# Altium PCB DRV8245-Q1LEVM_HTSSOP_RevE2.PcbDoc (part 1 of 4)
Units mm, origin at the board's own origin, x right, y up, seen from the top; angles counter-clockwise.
Board outline 81.9 x 103.6 mm, 4 copper layers (Top Layer, Signal Layer 1, Signal Layer 2, Bottom Layer), stack 1.554 mm thick; 187 components, 116 nets, 590 pads, 1182 vias.
Unrouted connection lines stored in the file: 116.
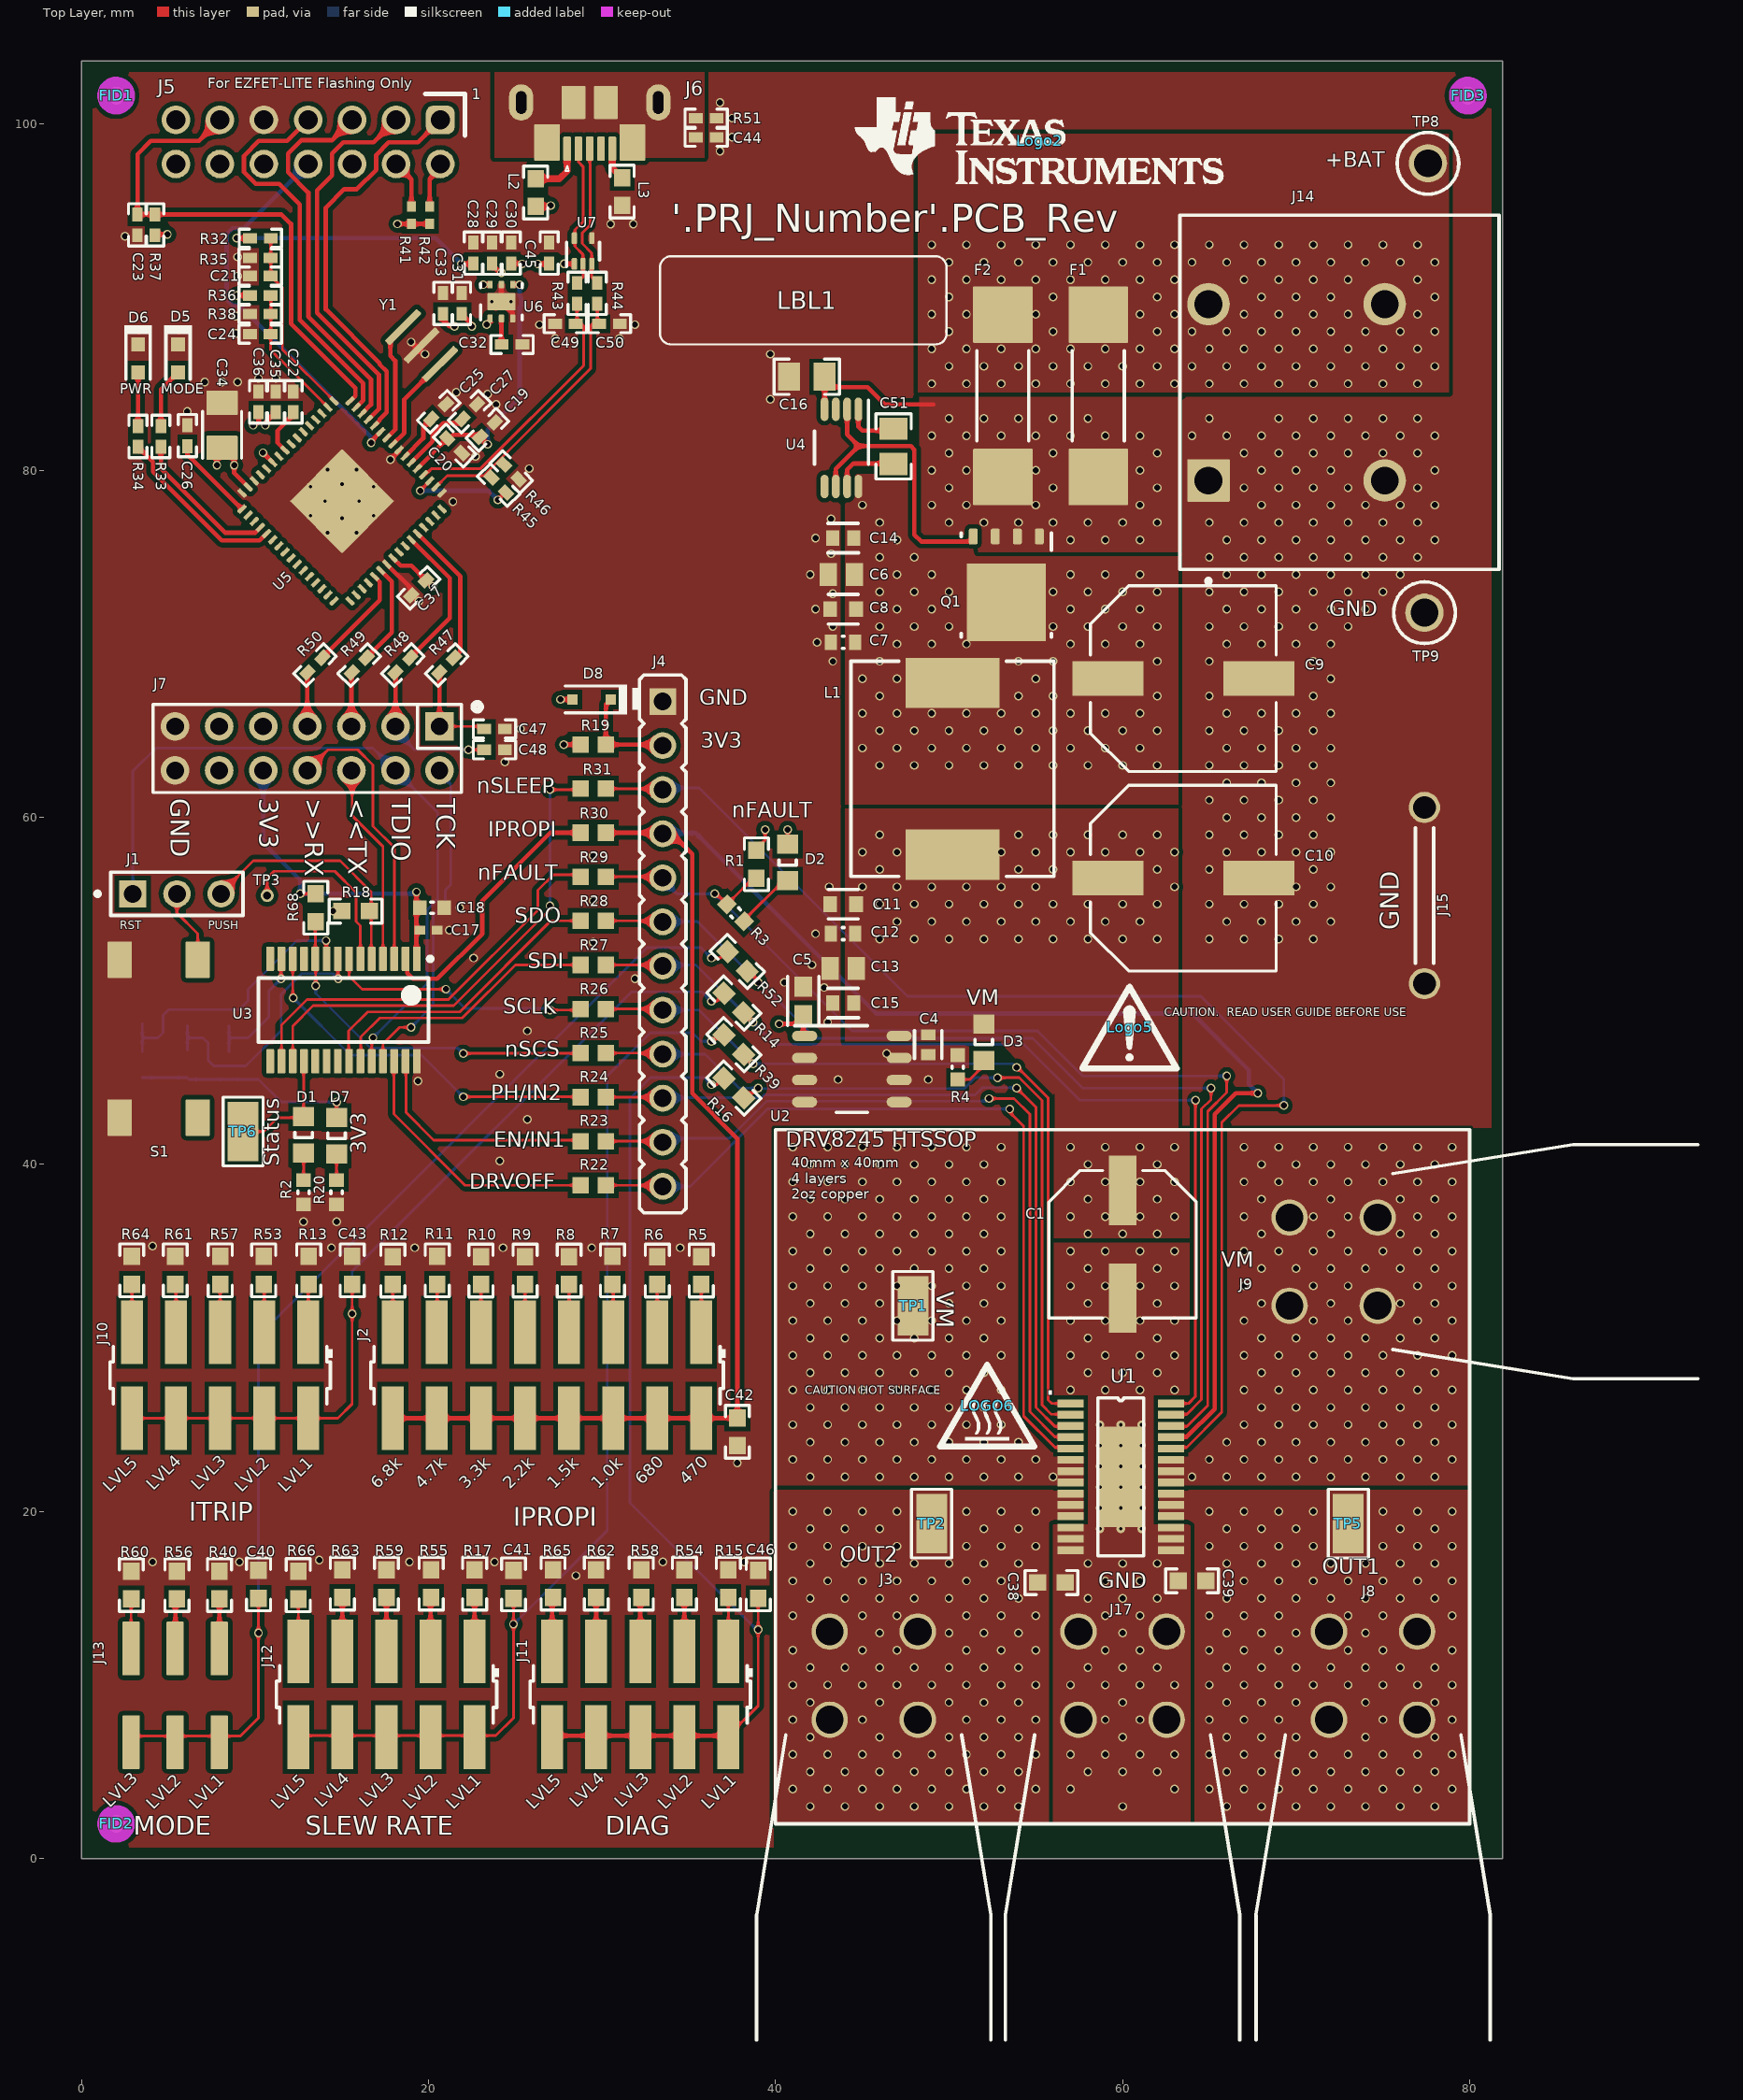
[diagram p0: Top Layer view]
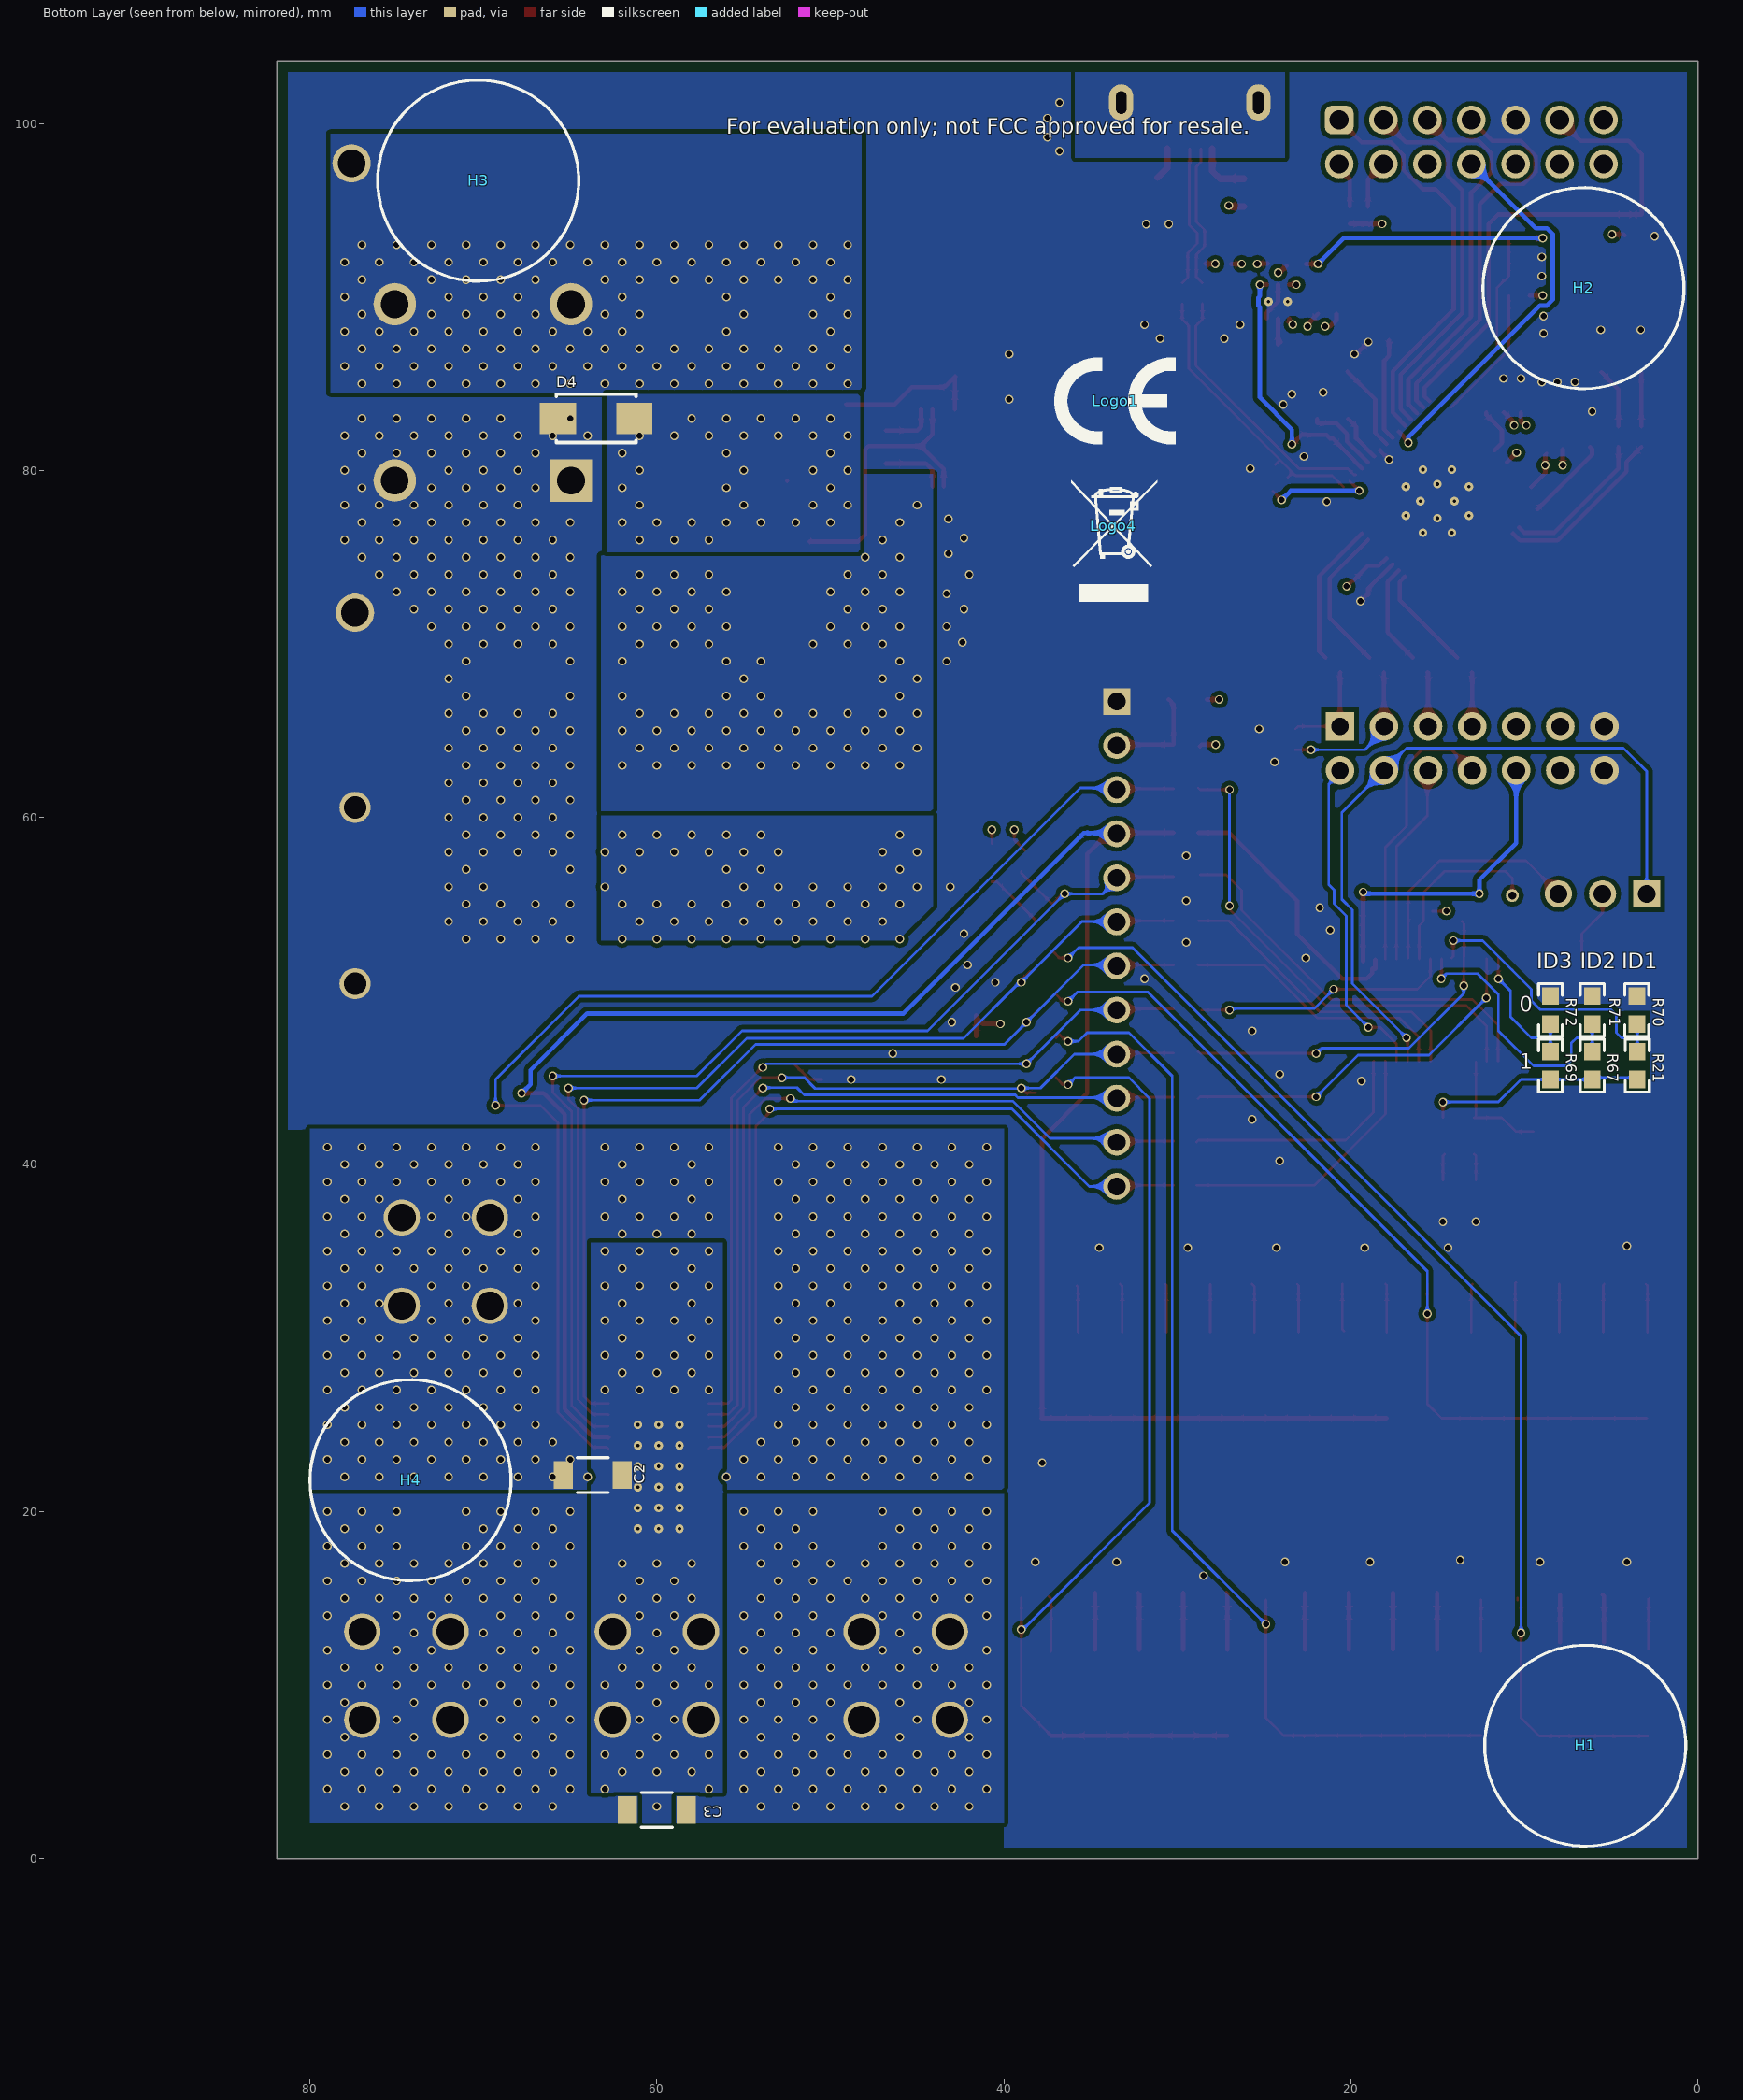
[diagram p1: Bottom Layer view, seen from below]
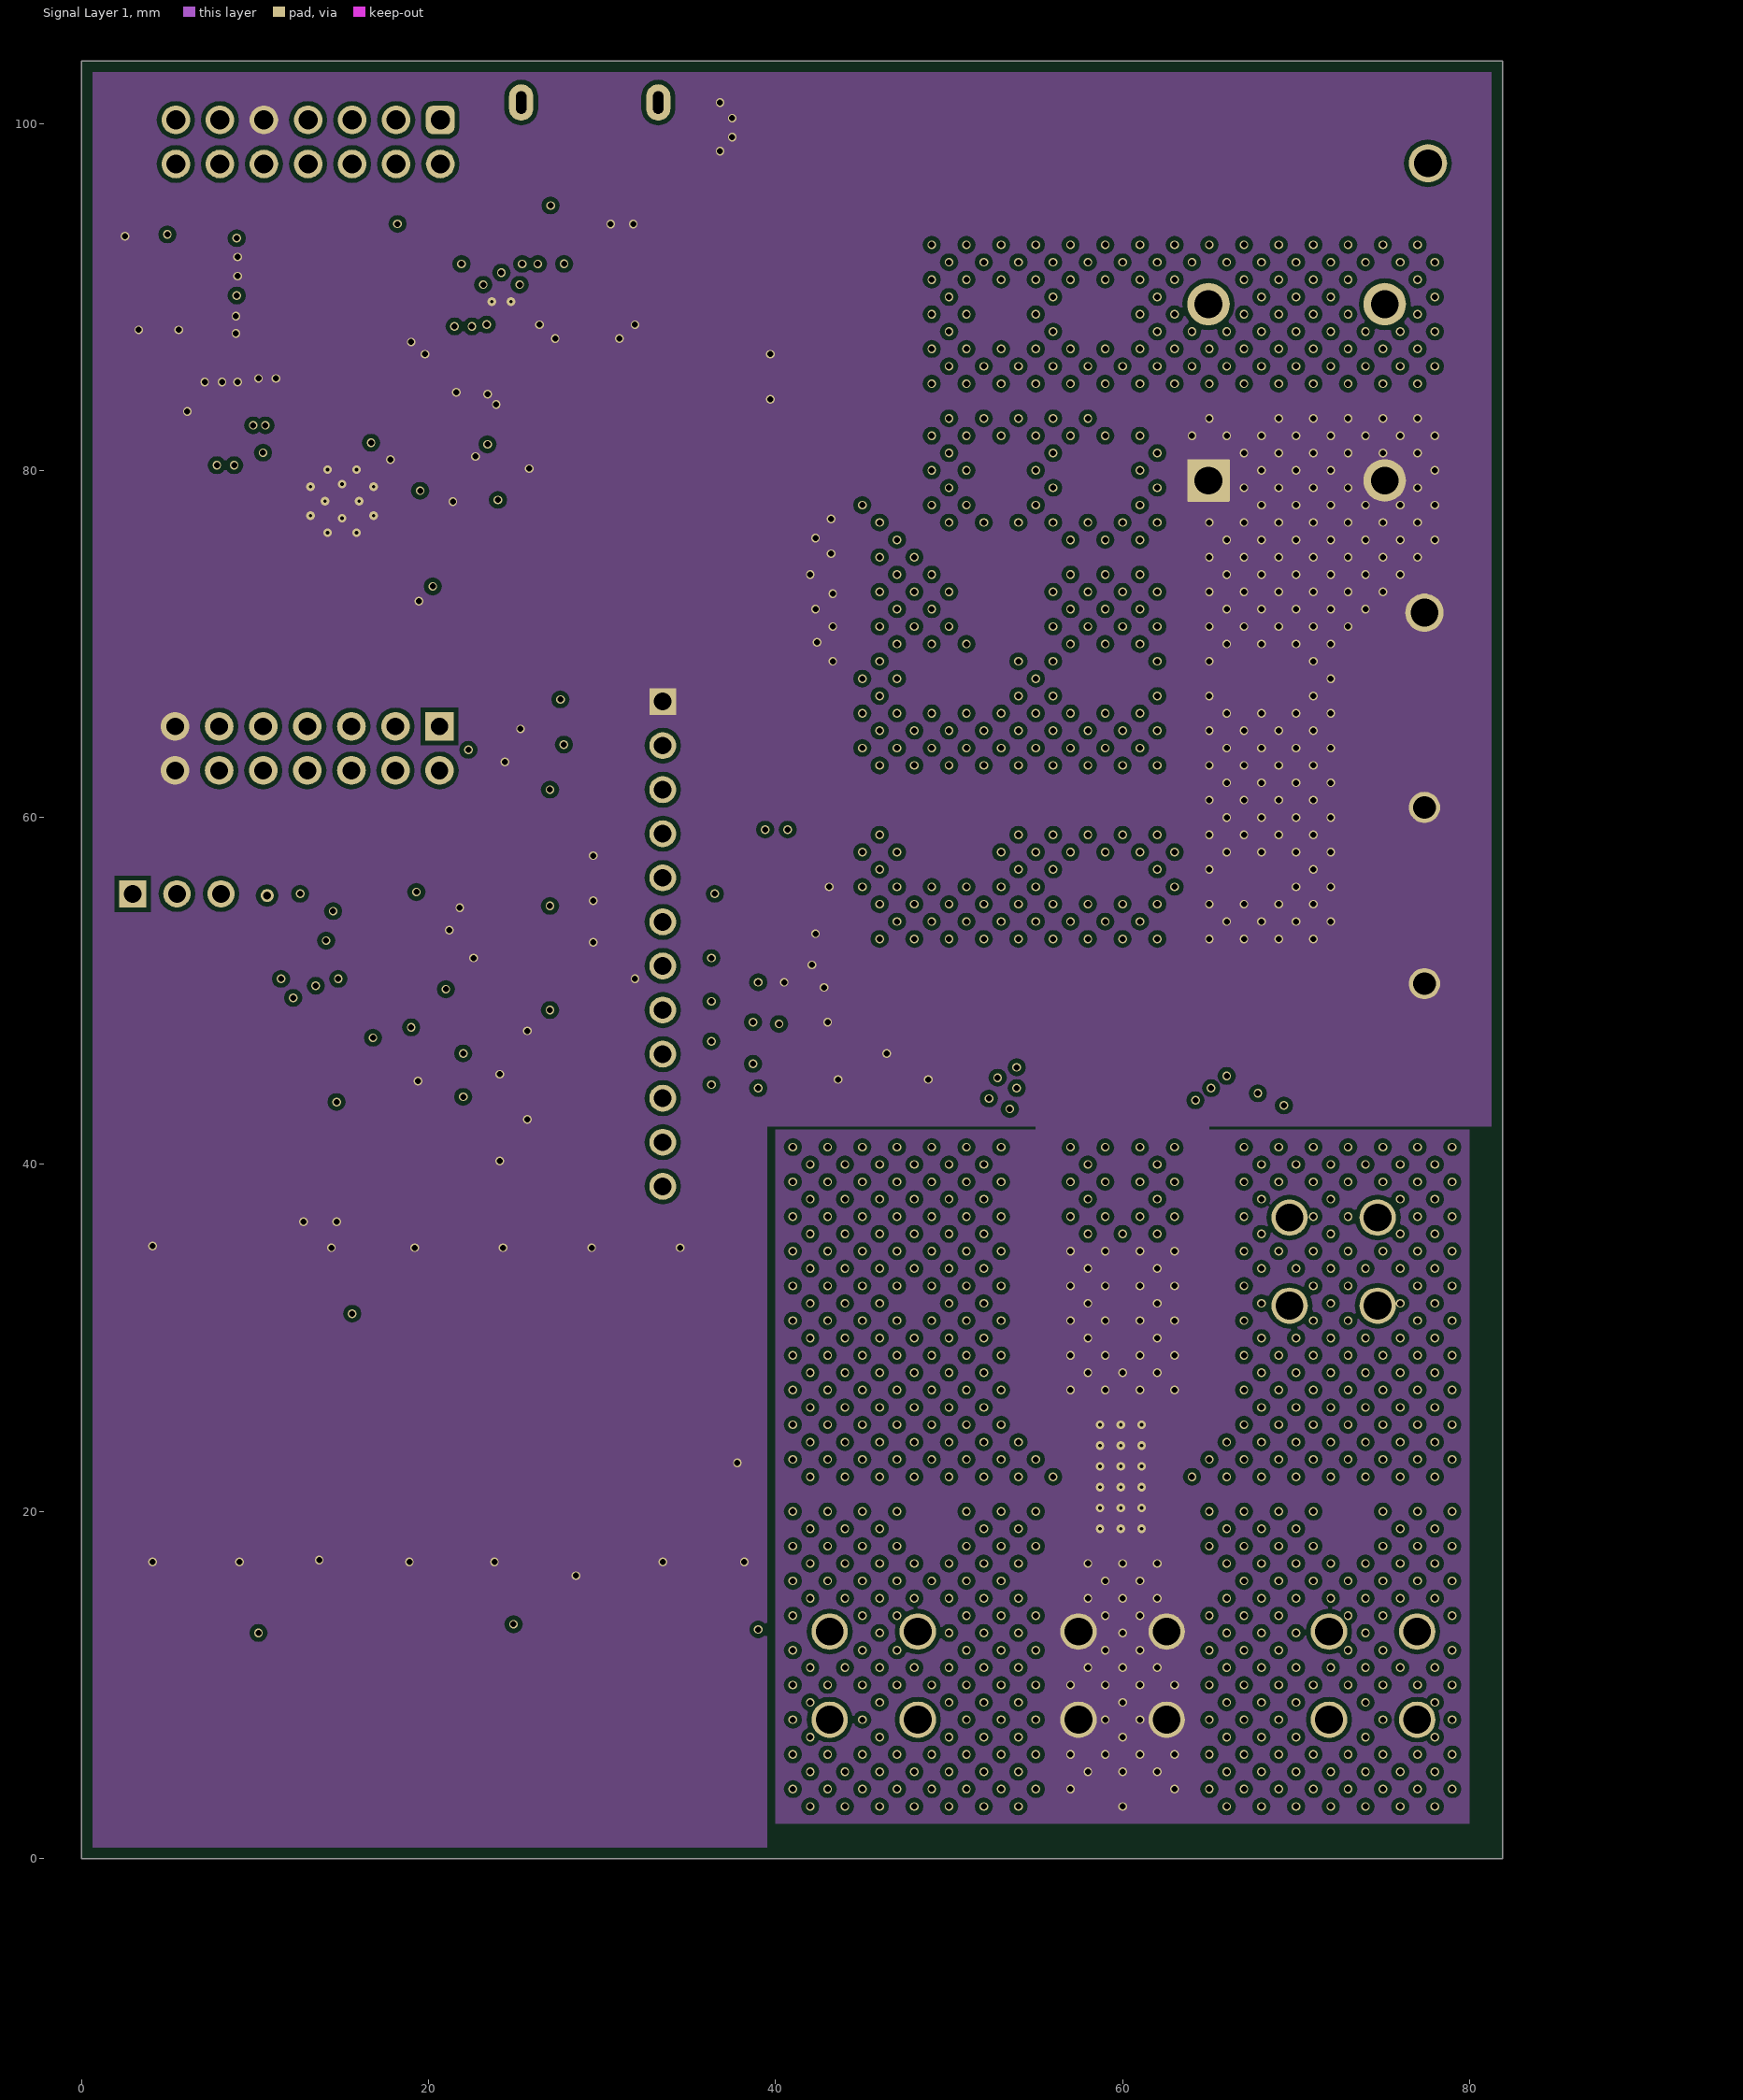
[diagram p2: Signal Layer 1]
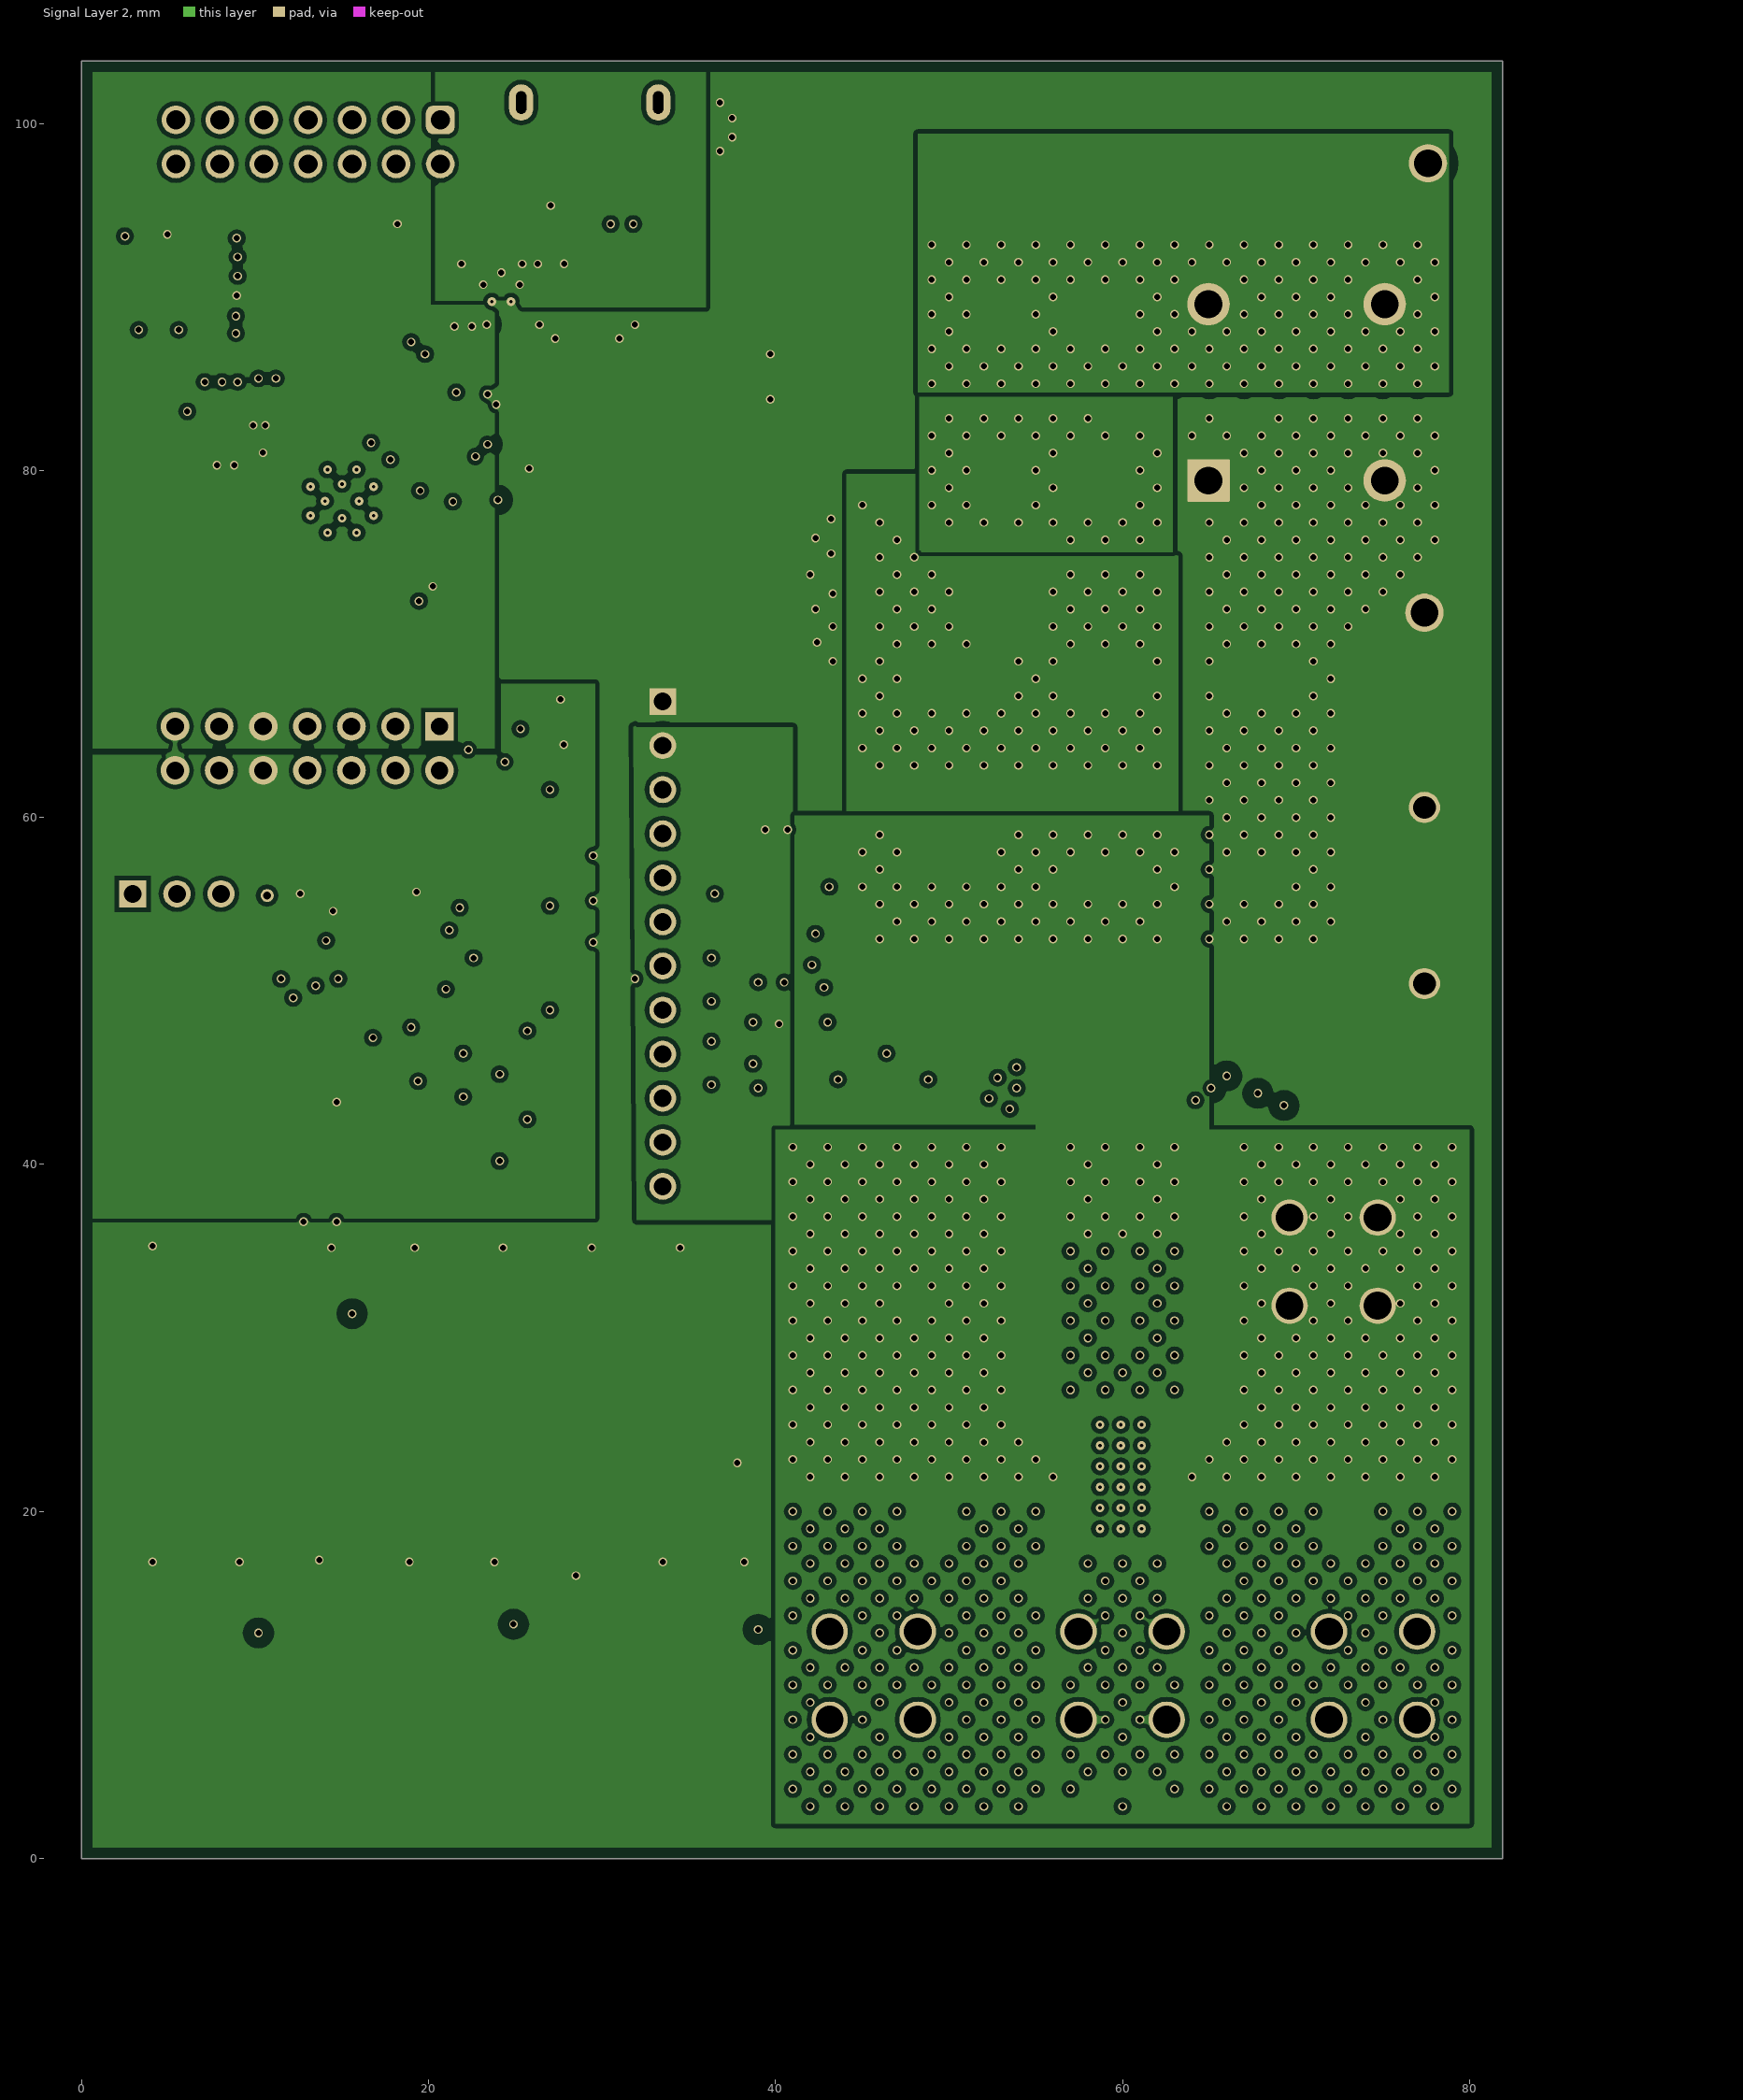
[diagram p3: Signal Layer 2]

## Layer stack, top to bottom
Top Solder: solder mask 0.0102, Solder Resist, Dk 3.5
Top Layer: signal copper 0.0711
Dielectric 1: prepreg 0.2896, FR4 370, Dk 4.2
Signal Layer 1: signal copper 0.0356
Dielectric 2: core 0.762, FR4 370, Dk 4.2
Signal Layer 2: signal copper 0.0356
Dielectric 3: prepreg 0.2896, FR4 370, Dk 4.2
Bottom Layer: signal copper 0.0711
Bottom Solder: solder mask 0.0102, Solder Resist, Dk 3.5

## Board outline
0,0 81.9,0 81.9,103.6 0,103.6

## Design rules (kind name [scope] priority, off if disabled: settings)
AcuteAngle [All] p1: minimum=4.50000000000000E+0001 checktracksonly=FALSE
AssemblyTestPointUsage [All] p1: valid=2
BoardOutlineClearance BoardOutlineClearance_MountingHoles [OnCopper and InComponentClass('Mounting Holes')] p1: gap=1 ignorepadtopadclearanceinfootprint=FALSE
BoardOutlineClearance BoardOutlineClearance_Poly [OnCopper and IsPoly] p2: gap=0.635 ignorepadtopadclearanceinfootprint=FALSE
BoardOutlineClearance [OnCopper and Not InComponentClass('Logo') and not InComponentClass('FiducialMark') and not InRegion(1000,500,4000,800) and not InPoly] p3: gap=1.905 ignorepadtopadclearanceinfootprint=FALSE
Clearance Clearance_92 [InNamedPolygon('TOP_LAYER_VM_P125')] p1: gap=0.254 ignorepadtopadclearanceinfootprint=TRUE except(0: Arc-Hole Track-Hole SMDPad-Hole THPad-Hole Via-Hole Fill-Hole Poly-Hole Region-Hole Text-Hole)
Clearance Clearance_91 [InNamedPolygon('TOP_LAYER_NONET_P-001')] p2: gap=0.254 ignorepadtopadclearanceinfootprint=TRUE except(0: Arc-Hole Track-Hole SMDPad-Hole THPad-Hole Via-Hole Fill-Hole Poly-Hole Region-Hole Text-Hole)
Clearance Clearance_90 [InNamedPolygon('BOTTOM_LAYER_OUT2_P211')] p3: gap=0.254 ignorepadtopadclearanceinfootprint=TRUE except(0: Arc-Hole Track-Hole SMDPad-Hole THPad-Hole Via-Hole Fill-Hole Poly-Hole Region-Hole Text-Hole)
Clearance Clearance_89 [InNamedPolygon('BOTTOM_LAYER_OUT1_P205')] p4: gap=0.254 ignorepadtopadclearanceinfootprint=TRUE except(0: Arc-Hole Track-Hole SMDPad-Hole THPad-Hole Via-Hole Fill-Hole Poly-Hole Region-Hole Text-Hole)
Clearance Clearance_88 [InNamedPolygon('BOTTOM_LAYER_OUT1_P205')] p5: gap=0.254 ignorepadtopadclearanceinfootprint=TRUE except(0: Arc-Hole Track-Hole SMDPad-Hole THPad-Hole Via-Hole Fill-Hole Poly-Hole Region-Hole Text-Hole)
Clearance Clearance_87 [InNamedPolygon('BOTTOM_LAYER_GND_P204')] p6: gap=0.254 ignorepadtopadclearanceinfootprint=TRUE except(0: Arc-Hole Track-Hole SMDPad-Hole THPad-Hole Via-Hole Fill-Hole Poly-Hole Region-Hole Text-Hole)
Clearance Clearance_86 [InNamedPolygon('TOP_LAYER_GND_P237')] p7: gap=0.254 ignorepadtopadclearanceinfootprint=TRUE except(0: Arc-Hole Track-Hole SMDPad-Hole THPad-Hole Via-Hole Fill-Hole Poly-Hole Region-Hole Text-Hole)
Clearance Clearance_85 [InNamedPolygon('TOP_LAYER_VM_P229')] p8: gap=0.254 ignorepadtopadclearanceinfootprint=TRUE except(0: Arc-Hole Track-Hole SMDPad-Hole THPad-Hole Via-Hole Fill-Hole Poly-Hole Region-Hole Text-Hole)
Clearance Clearance_84 [InNamedPolygon('TOP_LAYER_GND_P086')] p9: gap=0.254 ignorepadtopadclearanceinfootprint=TRUE except(0: Arc-Hole Track-Hole SMDPad-Hole THPad-Hole Via-Hole Fill-Hole Poly-Hole Region-Hole Text-Hole)
Clearance Clearance_83 [InNamedPolygon('TOP_LAYER_OUT1_P221')] p10: gap=0.1 ignorepadtopadclearanceinfootprint=TRUE except(0: Arc-Hole Track-Hole SMDPad-Hole THPad-Hole Via-Hole Fill-Hole Poly-Hole Region-Hole Text-Hole)
Clearance Clearance_82 [InNamedPolygon('TOP_LAYER_OUT2_P173')] p11: gap=0.254 ignorepadtopadclearanceinfootprint=TRUE except(0: Arc-Hole Track-Hole SMDPad-Hole THPad-Hole Via-Hole Fill-Hole Poly-Hole Region-Hole Text-Hole)
Clearance Clearance_81 [InNamedPolygon('TOP_LAYER_OUT2_P173')] p12: gap=0.254 ignorepadtopadclearanceinfootprint=TRUE except(0: Arc-Hole Track-Hole SMDPad-Hole THPad-Hole Via-Hole Fill-Hole Poly-Hole Region-Hole Text-Hole)
Clearance Clearance_80 [InNamedPolygon('TOP_LAYER_OUT2_P173')] p13: gap=0.254 ignorepadtopadclearanceinfootprint=TRUE except(0: Arc-Hole Track-Hole SMDPad-Hole THPad-Hole Via-Hole Fill-Hole Poly-Hole Region-Hole Text-Hole)
Clearance Clearance_79 [InNamedPolygon('TOP_LAYER_OUT1_P221')] p14: gap=0.254 ignorepadtopadclearanceinfootprint=TRUE except(0: Arc-Hole Track-Hole SMDPad-Hole THPad-Hole Via-Hole Fill-Hole Poly-Hole Region-Hole Text-Hole)
Clearance Clearance_78 [InNamedPolygon('TOP_LAYER_GND_P086')] p15: gap=0.254 ignorepadtopadclearanceinfootprint=TRUE except(0: Arc-Hole Track-Hole SMDPad-Hole THPad-Hole Via-Hole Fill-Hole Poly-Hole Region-Hole Text-Hole)
Clearance Clearance_77 [InNamedPolygon('TOP_LAYER_OUT1_P129')] p16: gap=0.254 ignorepadtopadclearanceinfootprint=TRUE except(0: Arc-Hole Track-Hole SMDPad-Hole THPad-Hole Via-Hole Fill-Hole Poly-Hole Region-Hole Text-Hole)
Clearance Clearance_76 [InNamedPolygon('TOP_LAYER_OUT2_P173')] p17: gap=0.254 ignorepadtopadclearanceinfootprint=TRUE except(0: Arc-Hole Track-Hole SMDPad-Hole THPad-Hole Via-Hole Fill-Hole Poly-Hole Region-Hole Text-Hole)
Clearance Clearance_75 [InNamedPolygon('TOP_LAYER_VM_P085')] p18: gap=0.254 ignorepadtopadclearanceinfootprint=TRUE except(0: Arc-Hole Track-Hole SMDPad-Hole THPad-Hole Via-Hole Fill-Hole Poly-Hole Region-Hole Text-Hole)
Clearance Clearance_74 [InNamedPolygon('TOP_LAYER_GND_P121')] p19: gap=0.254 ignorepadtopadclearanceinfootprint=TRUE except(0: Arc-Hole Track-Hole SMDPad-Hole THPad-Hole Via-Hole Fill-Hole Poly-Hole Region-Hole Text-Hole)
Clearance Clearance_73 [InNamedPolygon('TOP_LAYER_OUT1_P129') Or  InNamedPolygon('TOP_LAYER_OUT2_P173')] p20: gap=0.05 ignorepadtopadclearanceinfootprint=TRUE except(0: Arc-Hole Track-Hole SMDPad-Hole THPad-Hole Via-Hole Fill-Hole Poly-Hole Region-Hole Text-Hole)
Clearance Clearance_72 [InNamedPolygon('TOP_LAYER_OUT2_P173') Or  InNamedPolygon('TOP_LAYER_OUT1_P129')] p21: gap=0.1 ignorepadtopadclearanceinfootprint=TRUE except(0: Arc-Hole Track-Hole SMDPad-Hole THPad-Hole Via-Hole Fill-Hole Poly-Hole Region-Hole Text-Hole)
Clearance Clearance_71 [InNamedPolygon('TOP_LAYER_OUT2_P173')] p22: gap=0.254 ignorepadtopadclearanceinfootprint=TRUE except(0: Arc-Hole Track-Hole SMDPad-Hole THPad-Hole Via-Hole Fill-Hole Poly-Hole Region-Hole Text-Hole)
Clearance Clearance_70 [InNamedPolygon('TOP_LAYER_OUT1_P129')] p23: gap=0.254 ignorepadtopadclearanceinfootprint=TRUE except(0: Arc-Hole Track-Hole SMDPad-Hole THPad-Hole Via-Hole Fill-Hole Poly-Hole Region-Hole Text-Hole)
Clearance Clearance_69 [InNamedPolygon('TOP_LAYER_OUT2_P173')] p24: gap=0.1 ignorepadtopadclearanceinfootprint=TRUE except(0: Arc-Hole Track-Hole SMDPad-Hole THPad-Hole Via-Hole Fill-Hole Poly-Hole Region-Hole Text-Hole)
Clearance Clearance_68 [InNamedPolygon('TOP_LAYER_OUT1_P129')] p25: gap=0.1 ignorepadtopadclearanceinfootprint=TRUE except(0: Arc-Hole Track-Hole SMDPad-Hole THPad-Hole Via-Hole Fill-Hole Poly-Hole Region-Hole Text-Hole)
Clearance Clearance_67 [InNamedPolygon('TOP_LAYER_VM_P085')] p26: gap=0.1 ignorepadtopadclearanceinfootprint=TRUE except(0: Arc-Hole Track-Hole SMDPad-Hole THPad-Hole Via-Hole Fill-Hole Poly-Hole Region-Hole Text-Hole)
Clearance Clearance_66 [InNamedPolygon('BOTTOM_LAYER_P_IN_P174')] p27: gap=0.254 ignorepadtopadclearanceinfootprint=TRUE except(0: Arc-Hole Track-Hole SMDPad-Hole THPad-Hole Via-Hole Fill-Hole Poly-Hole Region-Hole Text-Hole)
Clearance Clearance_65 [InNamedPolygon('BOTTOM_LAYER_NETF1_2_P203')] p28: gap=0.254 ignorepadtopadclearanceinfootprint=TRUE except(0: Arc-Hole Track-Hole SMDPad-Hole THPad-Hole Via-Hole Fill-Hole Poly-Hole Region-Hole Text-Hole)
Clearance Clearance_64 [InNamedPolygon('BOTTOM_LAYER_VBAT_P165')] p29: gap=0.254 ignorepadtopadclearanceinfootprint=TRUE except(0: Arc-Hole Track-Hole SMDPad-Hole THPad-Hole Via-Hole Fill-Hole Poly-Hole Region-Hole Text-Hole)
Clearance Clearance_63 [InNamedPolygon('TOP_LAYER_VM_P167')] p30: gap=0.254 ignorepadtopadclearanceinfootprint=TRUE except(0: Arc-Hole Track-Hole SMDPad-Hole THPad-Hole Via-Hole Fill-Hole Poly-Hole Region-Hole Text-Hole)
Clearance Clearance_62 [InNamedPolygon('TOP_LAYER_VM_P167')] p31: gap=0.254 ignorepadtopadclearanceinfootprint=TRUE except(0: Arc-Hole Track-Hole SMDPad-Hole THPad-Hole Via-Hole Fill-Hole Poly-Hole Region-Hole Text-Hole)
Clearance Clearance_61 [InNamedPolygon('TOP_LAYER_VM_P171')] p32: gap=0.254 ignorepadtopadclearanceinfootprint=TRUE except(0: Arc-Hole Track-Hole SMDPad-Hole THPad-Hole Via-Hole Fill-Hole Poly-Hole Region-Hole Text-Hole)
Clearance Clearance_60 [InNamedPolygon('SIGNAL_LAYER_2_NETF1_2_P196')] p33: gap=0.254 ignorepadtopadclearanceinfootprint=TRUE except(0: Arc-Hole Track-Hole SMDPad-Hole THPad-Hole Via-Hole Fill-Hole Poly-Hole Region-Hole Text-Hole)
Clearance Clearance_59 [InNamedPolygon('SIGNAL_LAYER_2_VBAT_P197')] p34: gap=0.254 ignorepadtopadclearanceinfootprint=TRUE except(0: Arc-Hole Track-Hole SMDPad-Hole THPad-Hole Via-Hole Fill-Hole Poly-Hole Region-Hole Text-Hole)
Clearance Clearance_58 [InNamedPolygon('SIGNAL_LAYER_2_P_IN_P198')] p35: gap=0.254 ignorepadtopadclearanceinfootprint=TRUE except(0: Arc-Hole Track-Hole SMDPad-Hole THPad-Hole Via-Hole Fill-Hole Poly-Hole Region-Hole Text-Hole)
Clearance Clearance_57 [InNamedPolygon('SIGNAL_LAYER_2_3V3_P194')] p36: gap=0.254 ignorepadtopadclearanceinfootprint=TRUE except(0: Arc-Hole Track-Hole SMDPad-Hole THPad-Hole Via-Hole Fill-Hole Poly-Hole Region-Hole Text-Hole)
Clearance Clearance_56 [InNamedPolygon('TOP_LAYER_NETF1_2_P207')] p37: gap=0.254 ignorepadtopadclearanceinfootprint=TRUE except(0: Arc-Hole Track-Hole SMDPad-Hole THPad-Hole Via-Hole Fill-Hole Poly-Hole Region-Hole Text-Hole)
Clearance Clearance_55 [InNamedPolygon('TOP_LAYER_VBAT_P223')] p38: gap=0.254 ignorepadtopadclearanceinfootprint=TRUE except(0: Arc-Hole Track-Hole SMDPad-Hole THPad-Hole Via-Hole Fill-Hole Poly-Hole Region-Hole Text-Hole)
Clearance Clearance_54 [InNamedPolygon('TOP_LAYER_P_IN_P227')] p39: gap=0.254 ignorepadtopadclearanceinfootprint=TRUE except(0: Arc-Hole Track-Hole SMDPad-Hole THPad-Hole Via-Hole Fill-Hole Poly-Hole Region-Hole Text-Hole)
Clearance Clearance_53 [InNamedPolygon('TOP_LAYER_GND_P086')] p40: gap=0.254 ignorepadtopadclearanceinfootprint=TRUE except(0: Arc-Hole Track-Hole SMDPad-Hole THPad-Hole Via-Hole Fill-Hole Poly-Hole Region-Hole Text-Hole)
Clearance Clearance_52 [InNamedPolygon('SIGNAL_LAYER_2_VM_P177') Or  InNamedPolygon('SIGNAL_LAYER_2_VM_P179') Or  InNamedPolygon('SIGNAL_LAYER_2_VM_P160') Or  InNamedPolygon('SIGNAL_LAYER_2_VM_P175') Or  InNamedPolygon('SIGNAL_LAYER_2_VM_P181')] p41: gap=0.254 ignorepadtopadclearanceinfootprint=TRUE except(0: Arc-Hole Track-Hole SMDPad-Hole THPad-Hole Via-Hole Fill-Hole Poly-Hole Region-Hole Text-Hole)
Clearance Clearance_51 [InNamedPolygon('SIGNAL_LAYER_2_EZFET_VBUS_P136')] p42: gap=0.254 ignorepadtopadclearanceinfootprint=TRUE except(0: Arc-Hole Track-Hole SMDPad-Hole THPad-Hole Via-Hole Fill-Hole Poly-Hole Region-Hole Text-Hole)
Clearance Clearance_50 [InNamedPolygon('SIGNAL_LAYER_2_EZFET_VCC_P132')] p43: gap=0.254 ignorepadtopadclearanceinfootprint=TRUE except(0: Arc-Hole Track-Hole SMDPad-Hole THPad-Hole Via-Hole Fill-Hole Poly-Hole Region-Hole Text-Hole)
Clearance Clearance_49 [InNamedPolygon('SIGNAL_LAYER_2_3V3_MCU_P192')] p44: gap=0.254 ignorepadtopadclearanceinfootprint=TRUE except(0: Arc-Hole Track-Hole SMDPad-Hole THPad-Hole Via-Hole Fill-Hole Poly-Hole Region-Hole Text-Hole)
Clearance Clearance_48 [InNamedPolygon('SIGNAL_LAYER_1_GND_P190')] p45: gap=0.254 ignorepadtopadclearanceinfootprint=TRUE except(0: Arc-Hole Track-Hole SMDPad-Hole THPad-Hole Via-Hole Fill-Hole Poly-Hole Region-Hole Text-Hole)
Clearance Clearance_47 [InNamedPolygon('SIGNAL_LAYER_1_GND_P184')] p46: gap=0.254 ignorepadtopadclearanceinfootprint=TRUE except(0: Arc-Hole Track-Hole SMDPad-Hole THPad-Hole Via-Hole Fill-Hole Poly-Hole Region-Hole Text-Hole)
Clearance Clearance_46 [InNamedPolygon('BOTTOM_LAYER_GND_P241')] p47: gap=0.254 ignorepadtopadclearanceinfootprint=TRUE except(0: Arc-Hole Track-Hole SMDPad-Hole THPad-Hole Via-Hole Fill-Hole Poly-Hole Region-Hole Text-Hole)
Clearance Clearance_45 [InNamedPolygon('BOTTOM_LAYER_GND_P241')] p48: gap=0.254 ignorepadtopadclearanceinfootprint=TRUE except(0: Arc-Hole Track-Hole SMDPad-Hole THPad-Hole Via-Hole Fill-Hole Poly-Hole Region-Hole Text-Hole)
Clearance Clearance_44 [InNamedPolygon('BOTTOM_LAYER_OUT2_P163')] p49: gap=0.254 ignorepadtopadclearanceinfootprint=TRUE except(0: Arc-Hole Track-Hole SMDPad-Hole THPad-Hole Via-Hole Fill-Hole Poly-Hole Region-Hole Text-Hole)
Clearance Clearance_43 [InNamedPolygon('BOTTOM_LAYER_VM_P166')] p50: gap=0.254 ignorepadtopadclearanceinfootprint=TRUE except(0: Arc-Hole Track-Hole SMDPad-Hole THPad-Hole Via-Hole Fill-Hole Poly-Hole Region-Hole Text-Hole)
Clearance Clearance_42 [InNamedPolygon('BOTTOM_LAYER_VM_P235')] p51: gap=0.254 ignorepadtopadclearanceinfootprint=TRUE except(0: Arc-Hole Track-Hole SMDPad-Hole THPad-Hole Via-Hole Fill-Hole Poly-Hole Region-Hole Text-Hole)
Clearance Clearance_41 [InNamedPolygon('BOTTOM_LAYER_OUT1_P164')] p52: gap=0.254 ignorepadtopadclearanceinfootprint=TRUE except(0: Arc-Hole Track-Hole SMDPad-Hole THPad-Hole Via-Hole Fill-Hole Poly-Hole Region-Hole Text-Hole)
Clearance Clearance_40 [InNamedPolygon('BOTTOM_LAYER_GND_P162')] p53: gap=0.254 ignorepadtopadclearanceinfootprint=TRUE except(0: Arc-Hole Track-Hole SMDPad-Hole THPad-Hole Via-Hole Fill-Hole Poly-Hole Region-Hole Text-Hole)
Clearance Clearance_39 [InNamedPolygon('SIGNAL_LAYER_2_VM_P160')] p54: gap=0.254 ignorepadtopadclearanceinfootprint=TRUE except(0: Arc-Hole Track-Hole SMDPad-Hole THPad-Hole Via-Hole Fill-Hole Poly-Hole Region-Hole Text-Hole)
Clearance Clearance_38 [InNamedPolygon('SIGNAL_LAYER_2_NONET_P138')] p55: gap=0.254 ignorepadtopadclearanceinfootprint=TRUE except(0: Arc-Hole Track-Hole SMDPad-Hole THPad-Hole Via-Hole Fill-Hole Poly-Hole Region-Hole Text-Hole)
Clearance Clearance_37 [InNamedPolygon('SIGNAL_LAYER_1_VM_P146')] p56: gap=0.254 ignorepadtopadclearanceinfootprint=TRUE except(0: Arc-Hole Track-Hole SMDPad-Hole THPad-Hole Via-Hole Fill-Hole Poly-Hole Region-Hole Text-Hole)
Clearance Clearance_36 [InNamedPolygon('SIGNAL_LAYER_2_GND_P156')] p57: gap=0.254 ignorepadtopadclearanceinfootprint=TRUE except(0: Arc-Hole Track-Hole SMDPad-Hole THPad-Hole Via-Hole Fill-Hole Poly-Hole Region-Hole Text-Hole)
Clearance Clearance_35 [InNamedPolygon('SIGNAL_LAYER_1_VM_P148') Or  InNamedPolygon('SIGNAL_LAYER_1_VM_P148')] p58: gap=0.254 ignorepadtopadclearanceinfootprint=TRUE except(0: Arc-Hole Track-Hole SMDPad-Hole THPad-Hole Via-Hole Fill-Hole Poly-Hole Region-Hole Text-Hole)
Clearance Clearance_34 [InNamedPolygon('SIGNAL_LAYER_1_GND_P154')] p59: gap=0.254 ignorepadtopadclearanceinfootprint=TRUE except(0: Arc-Hole Track-Hole SMDPad-Hole THPad-Hole Via-Hole Fill-Hole Poly-Hole Region-Hole Text-Hole)
Clearance Clearance_33 [InNamedPolygon('SIGNAL_LAYER_2_NONET_P138')] p60: gap=0.254 ignorepadtopadclearanceinfootprint=TRUE except(0: Arc-Hole Track-Hole SMDPad-Hole THPad-Hole Via-Hole Fill-Hole Poly-Hole Region-Hole Text-Hole)
Clearance Clearance_32 [InNamedPolygon('SIGNAL_LAYER_2_GND_P082')] p61: gap=0.254 ignorepadtopadclearanceinfootprint=TRUE except(0: Arc-Hole Track-Hole SMDPad-Hole THPad-Hole Via-Hole Fill-Hole Poly-Hole Region-Hole Text-Hole)
Clearance Clearance_31 [InNamedPolygon('TOP_LAYER_GND_P076')] p62: gap=0.254 ignorepadtopadclearanceinfootprint=TRUE except(0: Arc-Hole Track-Hole SMDPad-Hole THPad-Hole Via-Hole Fill-Hole Poly-Hole Region-Hole Text-Hole)
Clearance Clearance_30 [InNamedPolygon('TOP_LAYER_GND_P087')] p63: gap=0.254 ignorepadtopadclearanceinfootprint=TRUE except(0: Arc-Hole Track-Hole SMDPad-Hole THPad-Hole Via-Hole Fill-Hole Poly-Hole Region-Hole Text-Hole)
Clearance Clearance_29 [InNamedPolygon('TOP_LAYER_VM_P127') Or  InNamedPolygon('TOP_LAYER_VM_P085')] p64: gap=0.254 ignorepadtopadclearanceinfootprint=TRUE except(0: Arc-Hole Track-Hole SMDPad-Hole THPad-Hole Via-Hole Fill-Hole Poly-Hole Region-Hole Text-Hole)
Clearance Clearance_28 [InNamedPolygon('TOP_LAYER_GND_P117')] p65: gap=0.254 ignorepadtopadclearanceinfootprint=TRUE except(0: Arc-Hole Track-Hole SMDPad-Hole THPad-Hole Via-Hole Fill-Hole Poly-Hole Region-Hole Text-Hole)
Clearance Clearance_27 [InNamedPolygon('TOP_LAYER_OUT1_P129') Or  InNamedPolygon('TOP_LAYER_OUT2_P173')] p66: gap=0.254 ignorepadtopadclearanceinfootprint=TRUE except(0: Arc-Hole Track-Hole SMDPad-Hole THPad-Hole Via-Hole Fill-Hole Poly-Hole Region-Hole Text-Hole)
Clearance Clearance_26 [InNamedPolygon('SIGNAL_LAYER_2_NONET_P113')] p67: gap=0.254 ignorepadtopadclearanceinfootprint=TRUE except(0: Arc-Hole Track-Hole SMDPad-Hole THPad-Hole Via-Hole Fill-Hole Poly-Hole Region-Hole Text-Hole)
Clearance Clearance_25 [InNamedPolygon('BOTTOM_LAYER_NONET_P115')] p68: gap=0.254 ignorepadtopadclearanceinfootprint=TRUE except(0: Arc-Hole Track-Hole SMDPad-Hole THPad-Hole Via-Hole Fill-Hole Poly-Hole Region-Hole Text-Hole)
Clearance Clearance_24 [InNamedPolygon('SIGNAL_LAYER_1_NONET_P111')] p69: gap=0.254 ignorepadtopadclearanceinfootprint=TRUE except(0: Arc-Hole Track-Hole SMDPad-Hole THPad-Hole Via-Hole Fill-Hole Poly-Hole Region-Hole Text-Hole)
Clearance Clearance_23 [InNamedPolygon('TOP_LAYER_NONET_P083')] p70: gap=0.254 ignorepadtopadclearanceinfootprint=TRUE except(0: Arc-Hole Track-Hole SMDPad-Hole THPad-Hole Via-Hole Fill-Hole Poly-Hole Region-Hole Text-Hole)
Clearance Clearance_22 [InNamedPolygon('TOP_LAYER_NONET_P105')] p71: gap=0.254 ignorepadtopadclearanceinfootprint=TRUE except(0: Arc-Hole Track-Hole SMDPad-Hole THPad-Hole Via-Hole Fill-Hole Poly-Hole Region-Hole Text-Hole)
Clearance Clearance_21 [InNamedPolygon('TOP_LAYER_OUT2_P107')] p72: gap=0.254 ignorepadtopadclearanceinfootprint=TRUE except(0: Arc-Hole Track-Hole SMDPad-Hole THPad-Hole Via-Hole Fill-Hole Poly-Hole Region-Hole Text-Hole)
Clearance Clearance_20 [InNamedPolygon('TOP_LAYER_NONET_P101')] p73: gap=0.254 ignorepadtopadclearanceinfootprint=TRUE except(0: Arc-Hole Track-Hole SMDPad-Hole THPad-Hole Via-Hole Fill-Hole Poly-Hole Region-Hole Text-Hole)
Clearance Clearance_19 [InNamedPolygon('TOP_LAYER_OUT1_P103')] p74: gap=0.254 ignorepadtopadclearanceinfootprint=TRUE except(0: Arc-Hole Track-Hole SMDPad-Hole THPad-Hole Via-Hole Fill-Hole Poly-Hole Region-Hole Text-Hole)
Clearance Clearance_18 [InNet('OUT1')] p75: gap=0.254 ignorepadtopadclearanceinfootprint=TRUE except(0: Arc-Hole Track-Hole SMDPad-Hole THPad-Hole Via-Hole Fill-Hole Poly-Hole Region-Hole Text-Hole)
Clearance Clearance_17 [InNamedPolygon('TOP_LAYER_OUT1_P000')] p76: gap=0.254 ignorepadtopadclearanceinfootprint=TRUE except(0: Arc-Hole Track-Hole SMDPad-Hole THPad-Hole Via-Hole Fill-Hole Poly-Hole Region-Hole Text-Hole)
Clearance Clearance_16 [InNamedPolygon('TOP_LAYER_OUT1_P000') vs InNet('OUT1')] p77: gap=0.1 ignorepadtopadclearanceinfootprint=TRUE except(0: Arc-Hole Track-Hole SMDPad-Hole THPad-Hole Via-Hole Fill-Hole Poly-Hole Region-Hole Text-Hole)
Clearance Clearance_15 [InNamedPolygon('TOP_LAYER_OUT1_P000')] p78: gap=0.1 ignorepadtopadclearanceinfootprint=TRUE except(0: Arc-Hole Track-Hole SMDPad-Hole THPad-Hole Via-Hole Fill-Hole Poly-Hole Region-Hole Text-Hole)
Clearance Clearance_14 [InNamedPolygon('TOP_LAYER_NONET_P093')] p79: gap=0.1 ignorepadtopadclearanceinfootprint=TRUE except(0: Arc-Hole Track-Hole SMDPad-Hole THPad-Hole Via-Hole Fill-Hole Poly-Hole Region-Hole Text-Hole)
Clearance Clearance_13 [InNamedPolygon('TOP_LAYER_NONET_P093')] p80: gap=0.254 ignorepadtopadclearanceinfootprint=TRUE except(0: Arc-Hole Track-Hole SMDPad-Hole THPad-Hole Via-Hole Fill-Hole Poly-Hole Region-Hole Text-Hole)
Clearance Clearance_12 [InNamedPolygon('TOP_LAYER_OUT2_P099')] p81: gap=0.254 ignorepadtopadclearanceinfootprint=TRUE except(0: Arc-Hole Track-Hole SMDPad-Hole THPad-Hole Via-Hole Fill-Hole Poly-Hole Region-Hole Text-Hole)
Clearance Clearance_11 [InNamedPolygon('TOP_LAYER_OUT2_P099')] p82: gap=0.254 ignorepadtopadclearanceinfootprint=TRUE except(0: Arc-Hole Track-Hole SMDPad-Hole THPad-Hole Via-Hole Fill-Hole Poly-Hole Region-Hole Text-Hole)
Clearance Clearance_10 [InNamedPolygon('TOP_LAYER_OUT1_P000')] p83: gap=0.254 ignorepadtopadclearanceinfootprint=TRUE except(0: Arc-Hole Track-Hole SMDPad-Hole THPad-Hole Via-Hole Fill-Hole Poly-Hole Region-Hole Text-Hole)
Clearance Clearance_9 [InNamedPolygon('TOP_LAYER_OUT1_P000')] p84: gap=0.254 ignorepadtopadclearanceinfootprint=TRUE except(0: Arc-Hole Track-Hole SMDPad-Hole THPad-Hole Via-Hole Fill-Hole Poly-Hole Region-Hole Text-Hole)
Clearance Clearance_8 [InNamedPolygon('BOTTOM_LAYER_NONET_P079') Or  InNamedPolygon('SIGNAL_LAYER_2_NONET_P078') Or  InNamedPolygon('SIGNAL_LAYER_1_NONET_P077') Or  InNamedPolygon('TOP_LAYER_NONET_P083') Or  InNamedPolygon('BOTTOM_LAYER_NONET_P072') Or  InNamedPolygon('SIGNAL_LAYER_2_NONET_P070') Or  InNamedPolygon('SIGNAL_LAYER_1_NONET_P059') Or  InNamedPolygon('TOP_LAYER_OUT2_P058') Or  InNamedPolygon('BOTTOM_LAYER_NONET_P056') Or  InNamedPolygon('SIGNAL_LAYER_2_NONET_P054') Or  InNamedPolygon('SIGNAL_LAYER_1_NONET_P052') Or  InNamedPolygon('TOP_LAYER_OUT1_P050') Or  InNamedPolygon('BOTTOM_LAYER_VM_P044') Or  InNamedPolygon('SIGNAL_LAYER_2_VM_P042') Or  InNamedPolygon('SIGNAL_LAYER_1_VM_P040') Or  InNamedPolygon('TOP_LAYER_VM_P038') Or  InNamedPolygon('BOTTOM_LAYER_VM_P036') Or  InNamedPolygon('SIGNAL_LAYER_2_VM_P018') Or  InNamedPolygon('SIGNAL_LAYER_1_VM_P016') Or  InNamedPolygon('TOP_LAYER_VM_P002')] p85: gap=0.254 ignorepadtopadclearanceinfootprint=TRUE except(0: Arc-Hole Track-Hole SMDPad-Hole THPad-Hole Via-Hole Fill-Hole Poly-Hole Region-Hole Text-Hole)
Clearance Clearance_7 [InNamedPolygon('TOP_LAYER_NONET_P089') Or  InNamedPolygon('TOP_LAYER_NONET_P090')] p86: gap=0.254 ignorepadtopadclearanceinfootprint=TRUE except(0: Arc-Hole Track-Hole SMDPad-Hole THPad-Hole Via-Hole Fill-Hole Poly-Hole Region-Hole Text-Hole)
Clearance Clearance_6 [InNamedPolygon('BOTTOM_LAYER_EZFET_USB_SHIELD_P002') Or  InNamedPolygon('TOP_LAYER_EZFET_USB_SHIELD_P201') Or  InNamedPolygon('SIGNAL_LAYER_2_EZFET_VBUS_P018') Or  InNamedPolygon('SIGNAL_LAYER_2_EZFET_VCC_P016')] p87: gap=0.254 ignorepadtopadclearanceinfootprint=TRUE except(0: Arc-Hole Track-Hole SMDPad-Hole THPad-Hole Via-Hole Fill-Hole Poly-Hole Region-Hole Text-Hole)
Clearance Clearance_5 [InNamedPolygon('TOP_LAYER_NONET_P072')] p88: gap=0.254 ignorepadtopadclearanceinfootprint=TRUE except(0: Arc-Hole Track-Hole SMDPad-Hole THPad-Hole Via-Hole Fill-Hole Poly-Hole Region-Hole Text-Hole)
Clearance Clearance_4 [InNamedPolygon('TOP_LAYER_VM_P123') Or  InNamedPolygon('TOP_LAYER_VM_P123') Or  InNamedPolygon('TOP_LAYER_VM_P123')] p89: gap=0.254 ignorepadtopadclearanceinfootprint=TRUE except(0: Arc-Hole Track-Hole SMDPad-Hole THPad-Hole Via-Hole Fill-Hole Poly-Hole Region-Hole Text-Hole)
Clearance Clearance_3 [InNamedPolygon('TOP_LAYER_VM_P042') Or  InNamedPolygon('TOP_LAYER_VM_P044') Or  InNamedPolygon('TOP_LAYER_OUT2_P040') Or  InNamedPolygon('TOP_LAYER_OUT1_P038')] p90: gap=0.254 ignorepadtopadclearanceinfootprint=TRUE except(0: Arc-Hole Track-Hole SMDPad-Hole THPad-Hole Via-Hole Fill-Hole Poly-Hole Region-Hole Text-Hole)
Clearance Clearance_2 [InNamedPolygon('TOP_LAYER_OUT2_P040')] p91: gap=0.254 ignorepadtopadclearanceinfootprint=TRUE except(0: Arc-Hole Track-Hole SMDPad-Hole THPad-Hole Via-Hole Fill-Hole Poly-Hole Region-Hole Text-Hole)
Clearance Clearance_1 [InNamedPolygon('TOP_LAYER_VM_P046')] p92: gap=0.152 ignorepadtopadclearanceinfootprint=TRUE except(0: Arc-Hole Track-Hole SMDPad-Hole THPad-Hole Via-Hole Fill-Hole Poly-Hole Region-Hole Text-Hole)
Clearance Clearance_Keepouts [((IsTrack Or IsArc) And Not InPoly) And IsFree and IsKeepOut vs ((IsTrack Or IsArc) And Not InPoly) And IsFree and IsKeepOut] p93: gap=0 ignorepadtopadclearanceinfootprint=FALSE
Clearance Clearance_Poly [InPolygon] p94: gap=0.635 ignorepadtopadclearanceinfootprint=TRUE
Clearance Clearance_FiducialMark [IsKeepOut and InComponentClass('FiducialMark') vs IsPad and InComponentClass('FiducialMark')] p95: gap=0 ignorepadtopadclearanceinfootprint=FALSE
Clearance [All] p96: gap=0.2 ignorepadtopadclearanceinfootprint=TRUE
ComponentClearance ComponentClearance_MountingHoles_FiducialMarks [InComponentClass('Mounting Holes') vs InComponentClass('FiducialMark')] p1: gap=1.27 collisioncheckmode=3 verticalgap=0.254 showdistances=FALSE
ComponentClearance ComponentClearance_Shunt [InComponentClass('Header') vs InComponentClass('Shunt')] p2: gap=0 collisioncheckmode=3 verticalgap=0 showdistances=FALSE
ComponentClearance ComponentClearance_Logo [InComponentClass('Logo')] p3: gap=1.27 collisioncheckmode=3 verticalgap=0.254 showdistances=FALSE
ComponentClearance ComponentClearance_ScrewToNut [(HasFootprint('NY PMS 440 0025 PH')) vs (HasFootprint('Keystone_1902C'))] p4: gap=0.127 collisioncheckmode=3 verticalgap=0.254 showdistances=FALSE
ComponentClearance ComponentClearance_MountingHoles [InComponentClass('Mounting Holes')] p5: gap=6.35 collisioncheckmode=3 verticalgap=2540 showdistances=FALSE
ComponentClearance ComponentClearance_SmallPassives [HasFootprint('0201*') or HasFootprint('0402*') or HasFootprint('0508') or HasFootprint('0603*') or HasFootprint('0612') or HasFootprint('0805*') or HasFootprint('0815*') or HasFootprint('0830*') or HasFootprint('1206*') or HasFootprint('1210*') or HasFootprint('1808*') or HasFootprint('1812*') or HasFootprint('1825*') or HasFootprint('2010*') or HasFootprint('2220*') or HasFootprint('2225*') or HasFootprint('2512*') or HasFootprint('2728*') or HasFootprint('3518*') vs HasFootprint('0201*') or HasFootprint('0402*') or HasFootprint('0508') or HasFootprint('0603*') or HasFootprint('0612') or HasFootprint('0805*') or HasFootprint('0815*') or HasFootprint('0830*') or HasFootprint('1206*') or HasFootprint('1210*') or HasFootprint('1808*') or HasFootprint('1812*') or HasFootprint('1825*') or HasFootprint('2010*') or HasFootprint('2220*') or HasFootprint('2225*') or HasFootprint('2512*') or HasFootprint('2728*') or HasFootprint('3518*')] p6: gap=0.38 collisioncheckmode=3 verticalgap=0.254 showdistances=FALSE
ComponentClearance ComponentClearance_THtoSMT [IsThruComponent vs IsSMTComponent] p7: gap=1.016 collisioncheckmode=3 verticalgap=0.762 showdistances=FALSE
ComponentClearance ComponentClearance_THtoTH [IsThruComponent vs IsThruComponent] p8: gap=0.762 collisioncheckmode=3 verticalgap=0.762 showdistances=FALSE
ComponentClearance [All] p9: gap=0.762 collisioncheckmode=3 verticalgap=0.254 showdistances=FALSE
DiffPairsRouting [All] p1: maxlimit=2.54 minlimit=0.254 mostfreqgap=0.254 toplayer_minwidth=0.16 toplayer_maxwidth=0.381 toplayer_prefwidth=0.254 midlayer1_minwidth=0.381 midlayer1_maxwidth=0.381 midlayer1_prefwidth=0.381 midlayer2_minwidth=0.381 midlayer2_maxwidth=0.381 midlayer2_prefwidth=0.381 bottomlayer_minwidth=0.16 bottomlayer_maxwidth=0.381 bottomlayer_prefwidth=0.254 maxuncoupledlength=25.4
FabricationTestPointUsage TestPointUsage [All] p1: valid=2 allowmultiple=FALSE
FabricationTestpoint Testpoint [All] p1: side=3 testpointundercomponent=TRUE minsize=1.016 maxsize=2.54 preferedsize=1.524 minholesize=0 maxholesize=1.016 preferedholesize=0.813 testpointgrid=0.025 allowsidetop=TRUE allowsidebottom=TRUE usegrid=TRUE gridtolerance=0
FanoutControl Fanout_LCC [IsLCC] p1: bgadir=Out bgaviamode=Centered fanoutstyle=Auto fanoutdirection=Alternating viagrid=0.025 // Fanout_LCC (Default Rule)
FanoutControl Fanout_BGA [IsBGA] p2: bgadir=Out bgaviamode=Centered fanoutstyle=Auto fanoutdirection=Alternating viagrid=0.025 // Fanout_BGA (Default Rule)
FanoutControl Fanout_Default [All] p4: bgadir=Out bgaviamode=Centered fanoutstyle=Auto fanoutdirection=Alternating viagrid=0.025 // Fanout_Default (Default Rule)
FanoutControl Fanout_Small [(CompPinCount < 5)] p5: bgadir=Out bgaviamode=Centered fanoutstyle=Auto fanoutdirection=OutThenIn viagrid=0.025 // Fanout_Small (Default Rule)
HoleSize [All] p1: absolutevalues=TRUE maxlimit=6.375 minlimit=0.2 maxpercent=80.000 minpercent=20.000
MinimumAnnularRing MinimumAnnularRing_ThermalPadVias [IsVia and InAnyComponent] p1: minimumring=0.15
MinimumAnnularRing [All] p2: minimumring=0.2
MinimumSolderMaskSliver MinimumSolderMaskSliver_Logo [InComponentClass('Logo') vs InComponentClass('Logo')] p1: minsoldermaskwidth=0.018
MinimumSolderMaskSliver [All] p2: minsoldermaskwidth=0.1
PlaneConnect [All] p1: planeconnectstyle=Relief reliefexpansion=0.254 reliefentries=4 reliefconductorwidth=0.254 reliefairgap=0.254
PolygonConnect PolygonConnect_87 [All vs IsNamedPolygon('TOP_LAYER_VM_P125')] p1: connectstyle=Direct reliefconductorwidth=0.254 reliefentries=4 polygonreliefangle="90 Angle" airgapwidth=0.254
PolygonConnect PolygonConnect_86 [All vs IsNamedPolygon('TOP_LAYER_NONET_P-001')] p2: connectstyle=Direct reliefconductorwidth=0.254 reliefentries=4 polygonreliefangle="90 Angle" airgapwidth=0.254
PolygonConnect PolygonConnect_85 [All vs IsNamedPolygon('BOTTOM_LAYER_OUT2_P211')] p3: connectstyle=Direct reliefconductorwidth=0.254 reliefentries=4 polygonreliefangle="90 Angle" airgapwidth=0.254
PolygonConnect PolygonConnect_84 [All vs IsNamedPolygon('BOTTOM_LAYER_OUT1_P205')] p4: connectstyle=Direct reliefconductorwidth=0.254 reliefentries=4 polygonreliefangle="90 Angle" airgapwidth=0.254
PolygonConnect PolygonConnect_83 [All vs IsNamedPolygon('BOTTOM_LAYER_OUT1_P205')] p5: connectstyle=Direct reliefconductorwidth=0.254 reliefentries=4 polygonreliefangle="90 Angle" airgapwidth=0.254
PolygonConnect PolygonConnect_82 [All vs IsNamedPolygon('BOTTOM_LAYER_GND_P204')] p6: connectstyle=Direct reliefconductorwidth=0.254 reliefentries=4 polygonreliefangle="90 Angle" airgapwidth=0.254
PolygonConnect PolygonConnect_81 [All vs IsNamedPolygon('TOP_LAYER_GND_P237')] p7: connectstyle=Direct reliefconductorwidth=0.254 reliefentries=4 polygonreliefangle="90 Angle" airgapwidth=0.254
PolygonConnect PolygonConnect_80 [All vs IsNamedPolygon('TOP_LAYER_GND_P086')] p8: connectstyle=Direct reliefconductorwidth=0.254 reliefentries=4 polygonreliefangle="90 Angle" airgapwidth=0.254
PolygonConnect PolygonConnect_79 [All vs IsNamedPolygon('TOP_LAYER_VM_P229')] p9: connectstyle=Direct reliefconductorwidth=0.254 reliefentries=4 polygonreliefangle="90 Angle" airgapwidth=0.254
PolygonConnect PolygonConnect_78 [All vs IsNamedPolygon('TOP_LAYER_GND_P086')] p10: connectstyle=Direct reliefconductorwidth=0.254 reliefentries=4 polygonreliefangle="90 Angle" airgapwidth=0.254
PolygonConnect PolygonConnect_77 [All vs IsNamedPolygon('TOP_LAYER_OUT1_P221')] p11: connectstyle=Direct reliefconductorwidth=0.254 reliefentries=4 polygonreliefangle="90 Angle" airgapwidth=0.254
PolygonConnect PolygonConnect_76 [All vs IsNamedPolygon('TOP_LAYER_OUT2_P173')] p12: connectstyle=Direct reliefconductorwidth=0.254 reliefentries=4 polygonreliefangle="90 Angle" airgapwidth=0.254
PolygonConnect PolygonConnect_75 [All vs IsNamedPolygon('TOP_LAYER_OUT2_P173')] p13: connectstyle=Direct reliefconductorwidth=0.254 reliefentries=4 polygonreliefangle="90 Angle" airgapwidth=0.254
PolygonConnect PolygonConnect_74 [All vs IsNamedPolygon('TOP_LAYER_OUT2_P173')] p14: connectstyle=Direct reliefconductorwidth=0.254 reliefentries=4 polygonreliefangle="90 Angle" airgapwidth=0.254
PolygonConnect PolygonConnect_73 [All vs IsNamedPolygon('TOP_LAYER_OUT1_P221')] p15: connectstyle=Direct reliefconductorwidth=0.254 reliefentries=4 polygonreliefangle="90 Angle" airgapwidth=0.254
PolygonConnect PolygonConnect_72 [All vs IsNamedPolygon('TOP_LAYER_GND_P121')] p16: connectstyle=Direct reliefconductorwidth=0.254 reliefentries=4 polygonreliefangle="90 Angle" airgapwidth=0.254
PolygonConnect PolygonConnect_71 [All vs IsNamedPolygon('TOP_LAYER_OUT2_P173') Or  IsNamedPolygon('TOP_LAYER_OUT1_P129')] p17: connectstyle=Direct reliefconductorwidth=0.254 reliefentries=4 polygonreliefangle="90 Angle" airgapwidth=0.254
PolygonConnect PolygonConnect_70 [All vs IsNamedPolygon('TOP_LAYER_OUT2_P173')] p18: connectstyle=Direct reliefconductorwidth=0.254 reliefentries=4 polygonreliefangle="90 Angle" airgapwidth=0.254
PolygonConnect PolygonConnect_69 [All vs IsNamedPolygon('TOP_LAYER_OUT1_P129')] p19: connectstyle=Direct reliefconductorwidth=0.254 reliefentries=4 polygonreliefangle="90 Angle" airgapwidth=0.254
PolygonConnect PolygonConnect_68 [All vs IsNamedPolygon('TOP_LAYER_VM_P085')] p20: connectstyle=Direct reliefconductorwidth=0.254 reliefentries=4 polygonreliefangle="90 Angle" airgapwidth=0.254
PolygonConnect PolygonConnect_67 [All vs IsNamedPolygon('BOTTOM_LAYER_P_IN_P174')] p21: connectstyle=Direct reliefconductorwidth=0.254 reliefentries=4 polygonreliefangle="90 Angle" airgapwidth=0.254
PolygonConnect PolygonConnect_66 [All vs IsNamedPolygon('BOTTOM_LAYER_NETF1_2_P203')] p22: connectstyle=Direct reliefconductorwidth=0.254 reliefentries=4 polygonreliefangle="90 Angle" airgapwidth=0.254
PolygonConnect PolygonConnect_65 [All vs IsNamedPolygon('BOTTOM_LAYER_VBAT_P165')] p23: connectstyle=Direct reliefconductorwidth=0.254 reliefentries=4 polygonreliefangle="90 Angle" airgapwidth=0.254
PolygonConnect PolygonConnect_64 [All vs IsNamedPolygon('TOP_LAYER_VM_P167')] p24: connectstyle=Direct reliefconductorwidth=0.254 reliefentries=4 polygonreliefangle="90 Angle" airgapwidth=0.254
PolygonConnect PolygonConnect_63 [All vs IsNamedPolygon('TOP_LAYER_VM_P167')] p25: connectstyle=Direct reliefconductorwidth=0.254 reliefentries=4 polygonreliefangle="90 Angle" airgapwidth=0.254
PolygonConnect PolygonConnect_62 [All vs IsNamedPolygon('TOP_LAYER_VM_P171')] p26: connectstyle=Direct reliefconductorwidth=0.254 reliefentries=4 polygonreliefangle="90 Angle" airgapwidth=0.254
PolygonConnect PolygonConnect_61 [All vs IsNamedPolygon('SIGNAL_LAYER_2_GND_P199')] p27: connectstyle=Direct reliefconductorwidth=0.254 reliefentries=4 polygonreliefangle="90 Angle" airgapwidth=0.254
PolygonConnect PolygonConnect_60 [All vs IsNamedPolygon('SIGNAL_LAYER_2_NETF1_2_P196')] p28: connectstyle=Direct reliefconductorwidth=0.254 reliefentries=4 polygonreliefangle="90 Angle" airgapwidth=0.254
PolygonConnect PolygonConnect_59 [All vs IsNamedPolygon('SIGNAL_LAYER_2_VBAT_P197')] p29: connectstyle=Direct reliefconductorwidth=0.254 reliefentries=4 polygonreliefangle="90 Angle" airgapwidth=0.254
PolygonConnect PolygonConnect_58 [All vs IsNamedPolygon('SIGNAL_LAYER_2_P_IN_P198')] p30: connectstyle=Direct reliefconductorwidth=0.254 reliefentries=4 polygonreliefangle="90 Angle" airgapwidth=0.254
PolygonConnect PolygonConnect_57 [All vs IsNamedPolygon('SIGNAL_LAYER_2_3V3_P194')] p31: connectstyle=Direct reliefconductorwidth=0.254 reliefentries=4 polygonreliefangle="90 Angle" airgapwidth=0.254
PolygonConnect PolygonConnect_56 [All vs IsNamedPolygon('TOP_LAYER_NETF1_2_P207')] p32: connectstyle=Direct reliefconductorwidth=0.254 reliefentries=4 polygonreliefangle="90 Angle" airgapwidth=0.254
PolygonConnect PolygonConnect_55 [All vs IsNamedPolygon('TOP_LAYER_VBAT_P223')] p33: connectstyle=Direct reliefconductorwidth=0.254 reliefentries=4 polygonreliefangle="90 Angle" airgapwidth=0.254
PolygonConnect PolygonConnect_54 [All vs IsNamedPolygon('TOP_LAYER_P_IN_P227')] p34: connectstyle=Direct reliefconductorwidth=0.254 reliefentries=4 polygonreliefangle="90 Angle" airgapwidth=0.254
PolygonConnect PolygonConnect_53 [All vs IsNamedPolygon('TOP_LAYER_GND_P086')] p35: connectstyle=Direct reliefconductorwidth=0.254 reliefentries=4 polygonreliefangle="90 Angle" airgapwidth=0.254
PolygonConnect PolygonConnect_52 [All vs IsNamedPolygon('SIGNAL_LAYER_2_VM_P177') Or  IsNamedPolygon('SIGNAL_LAYER_2_VM_P179') Or  IsNamedPolygon('SIGNAL_LAYER_2_VM_P160') Or  IsNamedPolygon('SIGNAL_LAYER_2_VM_P175') Or  IsNamedPolygon('SIGNAL_LAYER_2_VM_P181')] p36: connectstyle=Direct reliefconductorwidth=0.254 reliefentries=4 polygonreliefangle="90 Angle" airgapwidth=0.254
PolygonConnect PolygonConnect_51 [All vs IsNamedPolygon('SIGNAL_LAYER_2_EZFET_VBUS_P136')] p37: connectstyle=Direct reliefconductorwidth=0.254 reliefentries=4 polygonreliefangle="90 Angle" airgapwidth=0.254
PolygonConnect PolygonConnect_50 [All vs IsNamedPolygon('SIGNAL_LAYER_2_EZFET_VCC_P132')] p38: connectstyle=Direct reliefconductorwidth=0.254 reliefentries=4 polygonreliefangle="90 Angle" airgapwidth=0.254
PolygonConnect PolygonConnect_49 [All vs IsNamedPolygon('SIGNAL_LAYER_2_3V3_MCU_P192')] p39: connectstyle=Direct reliefconductorwidth=0.254 reliefentries=4 polygonreliefangle="90 Angle" airgapwidth=0.254
PolygonConnect PolygonConnect_48 [All vs IsNamedPolygon('SIGNAL_LAYER_1_GND_P190')] p40: connectstyle=Direct reliefconductorwidth=0.254 reliefentries=4 polygonreliefangle="90 Angle" airgapwidth=0.254
PolygonConnect PolygonConnect_47 [All vs IsNamedPolygon('SIGNAL_LAYER_1_GND_P184')] p41: connectstyle=Direct reliefconductorwidth=0.254 reliefentries=4 polygonreliefangle="90 Angle" airgapwidth=0.254
PolygonConnect PolygonConnect_46 [All vs IsNamedPolygon('BOTTOM_LAYER_GND_P241')] p42: connectstyle=Direct reliefconductorwidth=0.254 reliefentries=4 polygonreliefangle="90 Angle" airgapwidth=0.254
PolygonConnect PolygonConnect_45 [All vs IsNamedPolygon('BOTTOM_LAYER_GND_P241')] p43: connectstyle=Direct reliefconductorwidth=0.254 reliefentries=4 polygonreliefangle="90 Angle" airgapwidth=0.254
PolygonConnect PolygonConnect_44 [All vs IsNamedPolygon('BOTTOM_LAYER_OUT2_P163')] p44: connectstyle=Direct reliefconductorwidth=0.254 reliefentries=4 polygonreliefangle="90 Angle" airgapwidth=0.254
PolygonConnect PolygonConnect_43 [All vs IsNamedPolygon('BOTTOM_LAYER_VM_P166')] p45: connectstyle=Direct reliefconductorwidth=0.254 reliefentries=4 polygonreliefangle="90 Angle" airgapwidth=0.254
PolygonConnect PolygonConnect_42 [All vs IsNamedPolygon('BOTTOM_LAYER_VM_P235')] p46: connectstyle=Direct reliefconductorwidth=0.254 reliefentries=4 polygonreliefangle="90 Angle" airgapwidth=0.254
PolygonConnect PolygonConnect_41 [All vs IsNamedPolygon('BOTTOM_LAYER_OUT1_P164')] p47: connectstyle=Direct reliefconductorwidth=0.254 reliefentries=4 polygonreliefangle="90 Angle" airgapwidth=0.254
PolygonConnect PolygonConnect_40 [All vs IsNamedPolygon('BOTTOM_LAYER_GND_P162')] p48: connectstyle=Direct reliefconductorwidth=0.254 reliefentries=4 polygonreliefangle="90 Angle" airgapwidth=0.254
PolygonConnect PolygonConnect_39 [All vs IsNamedPolygon('SIGNAL_LAYER_2_VM_P160')] p49: connectstyle=Direct reliefconductorwidth=0.254 reliefentries=4 polygonreliefangle="90 Angle" airgapwidth=0.254
PolygonConnect PolygonConnect_38 [All vs IsNamedPolygon('SIGNAL_LAYER_2_NONET_P138')] p50: connectstyle=Direct reliefconductorwidth=0.254 reliefentries=4 polygonreliefangle="90 Angle" airgapwidth=0.254
PolygonConnect PolygonConnect_37 [All vs IsNamedPolygon('SIGNAL_LAYER_1_VM_P146')] p51: connectstyle=Direct reliefconductorwidth=0.254 reliefentries=4 polygonreliefangle="90 Angle" airgapwidth=0.254
PolygonConnect PolygonConnect_36 [All vs IsNamedPolygon('SIGNAL_LAYER_2_GND_P156')] p52: connectstyle=Direct reliefconductorwidth=0.254 reliefentries=4 polygonreliefangle="90 Angle" airgapwidth=0.254
PolygonConnect PolygonConnect_35 [All vs IsNamedPolygon('BOTTOM_LAYER_EZFET_USB_SHIELD_P219')] p53: connectstyle=Direct reliefconductorwidth=0.254 reliefentries=4 polygonreliefangle="90 Angle" airgapwidth=0.254
PolygonConnect PolygonConnect_34 [All vs IsNamedPolygon('SIGNAL_LAYER_1_VM_P144')] p54: connectstyle=Direct reliefconductorwidth=0.254 reliefentries=4 polygonreliefangle="90 Angle" airgapwidth=0.254
PolygonConnect PolygonConnect_33 [All vs IsNamedPolygon('SIGNAL_LAYER_1_VM_P148') Or  IsNamedPolygon('SIGNAL_LAYER_1_VM_P148')] p55: connectstyle=Direct reliefconductorwidth=0.254 reliefentries=4 polygonreliefangle="90 Angle" airgapwidth=0.254
PolygonConnect PolygonConnect_32 [All vs IsNamedPolygon('SIGNAL_LAYER_1_GND_P154')] p56: connectstyle=Direct reliefconductorwidth=0.254 reliefentries=4 polygonreliefangle="90 Angle" airgapwidth=0.254
PolygonConnect PolygonConnect_31 [All vs IsNamedPolygon('SIGNAL_LAYER_2_NONET_P138')] p57: connectstyle=Direct reliefconductorwidth=0.254 reliefentries=4 polygonreliefangle="90 Angle" airgapwidth=0.254
PolygonConnect PolygonConnect_30 [All vs IsNamedPolygon('SIGNAL_LAYER_2_GND_P082')] p58: connectstyle=Direct reliefconductorwidth=0.254 reliefentries=4 polygonreliefangle="90 Angle" airgapwidth=0.254
PolygonConnect PolygonConnect_29 [All vs IsNamedPolygon('TOP_LAYER_GND_P076')] p59: connectstyle=Direct reliefconductorwidth=0.254 reliefentries=4 polygonreliefangle="90 Angle" airgapwidth=0.254
PolygonConnect PolygonConnect_28 [All vs IsNamedPolygon('TOP_LAYER_GND_P087')] p60: connectstyle=Direct reliefconductorwidth=0.254 reliefentries=4 polygonreliefangle="90 Angle" airgapwidth=0.254
PolygonConnect PolygonConnect_27 [All vs IsNamedPolygon('TOP_LAYER_VM_P127') Or  IsNamedPolygon('TOP_LAYER_VM_P085')] p61: connectstyle=Direct reliefconductorwidth=0.254 reliefentries=4 polygonreliefangle="90 Angle" airgapwidth=0.254
PolygonConnect PolygonConnect_26 [All vs IsNamedPolygon('TOP_LAYER_GND_P117')] p62: connectstyle=Direct reliefconductorwidth=0.254 reliefentries=4 polygonreliefangle="90 Angle" airgapwidth=0.254
PolygonConnect PolygonConnect_25 [All vs IsNamedPolygon('TOP_LAYER_OUT1_P129') Or  IsNamedPolygon('TOP_LAYER_OUT2_P173')] p63: connectstyle=Direct reliefconductorwidth=0.254 reliefentries=4 polygonreliefangle="90 Angle" airgapwidth=0.254
PolygonConnect PolygonConnect_24 [All vs IsNamedPolygon('SIGNAL_LAYER_2_NONET_P113')] p64: connectstyle=Direct reliefconductorwidth=0.254 reliefentries=4 polygonreliefangle="90 Angle" airgapwidth=0.254
PolygonConnect PolygonConnect_23 [All vs IsNamedPolygon('BOTTOM_LAYER_NONET_P115')] p65: connectstyle=Direct reliefconductorwidth=0.254 reliefentries=4 polygonreliefangle="90 Angle" airgapwidth=0.254
PolygonConnect PolygonConnect_22 [All vs IsNamedPolygon('SIGNAL_LAYER_1_NONET_P111')] p66: connectstyle=Direct reliefconductorwidth=0.254 reliefentries=4 polygonreliefangle="90 Angle" airgapwidth=0.254
PolygonConnect PolygonConnect_21 [All vs IsNamedPolygon('TOP_LAYER_NONET_P083')] p67: connectstyle=Direct reliefconductorwidth=0.254 reliefentries=4 polygonreliefangle="90 Angle" airgapwidth=0.254
PolygonConnect PolygonConnect_20 [All vs IsNamedPolygon('TOP_LAYER_NONET_P105')] p68: connectstyle=Direct reliefconductorwidth=0.254 reliefentries=4 polygonreliefangle="90 Angle" airgapwidth=0.254
PolygonConnect PolygonConnect_19 [All vs IsNamedPolygon('TOP_LAYER_OUT2_P107')] p69: connectstyle=Direct reliefconductorwidth=0.254 reliefentries=4 polygonreliefangle="90 Angle" airgapwidth=0.254
PolygonConnect PolygonConnect_18 [All vs IsNamedPolygon('TOP_LAYER_NONET_P101')] p70: connectstyle=Direct reliefconductorwidth=0.254 reliefentries=4 polygonreliefangle="90 Angle" airgapwidth=0.254
PolygonConnect PolygonConnect_17 [All vs IsNamedPolygon('TOP_LAYER_OUT1_P103')] p71: connectstyle=Direct reliefconductorwidth=0.254 reliefentries=4 polygonreliefangle="90 Angle" airgapwidth=0.254
PolygonConnect PolygonConnect_16 [All vs IsNamedPolygon('TOP_LAYER_OUT1_P000')] p72: connectstyle=Direct reliefconductorwidth=0.254 reliefentries=4 polygonreliefangle="90 Angle" airgapwidth=0.254
PolygonConnect PolygonConnect_15 [All vs IsNamedPolygon('TOP_LAYER_NONET_P093')] p73: connectstyle=Direct reliefconductorwidth=0.254 reliefentries=4 polygonreliefangle="90 Angle" airgapwidth=0.254
PolygonConnect PolygonConnect_14 [All vs IsNamedPolygon('TOP_LAYER_OUT2_P099')] p74: connectstyle=Direct reliefconductorwidth=0.254 reliefentries=4 polygonreliefangle="90 Angle" airgapwidth=0.254
PolygonConnect PolygonConnect_13 [All vs IsNamedPolygon('TOP_LAYER_OUT1_P000')] p75: connectstyle=Direct reliefconductorwidth=0.254 reliefentries=4 polygonreliefangle="90 Angle" airgapwidth=0.254
PolygonConnect PolygonConnect_12 [All vs IsNamedPolygon('BOTTOM_LAYER_NONET_P079') Or  IsNamedPolygon('SIGNAL_LAYER_2_NONET_P078') Or  IsNamedPolygon('SIGNAL_LAYER_1_NONET_P077') Or  IsNamedPolygon('TOP_LAYER_NONET_P083') Or  IsNamedPolygon('BOTTOM_LAYER_NONET_P072') Or  IsNamedPolygon('SIGNAL_LAYER_2_NONET_P070') Or  IsNamedPolygon('SIGNAL_LAYER_1_NONET_P059') Or  IsNamedPolygon('TOP_LAYER_OUT2_P058') Or  IsNamedPolygon('BOTTOM_LAYER_NONET_P056') Or  IsNamedPolygon('SIGNAL_LAYER_2_NONET_P054') Or  IsNamedPolygon('SIGNAL_LAYER_1_NONET_P052') Or  IsNamedPolygon('TOP_LAYER_OUT1_P050') Or  IsNamedPolygon('BOTTOM_LAYER_VM_P044') Or  IsNamedPolygon('SIGNAL_LAYER_2_VM_P042') Or  IsNamedPolygon('SIGNAL_LAYER_1_VM_P040') Or  IsNamedPolygon('TOP_LAYER_VM_P038') Or  IsNamedPolygon('BOTTOM_LAYER_VM_P036') Or  IsNamedPolygon('SIGNAL_LAYER_2_VM_P018') Or  IsNamedPolygon('SIGNAL_LAYER_1_VM_P016') Or  IsNamedPolygon('TOP_LAYER_VM_P002')] p76: connectstyle=Direct reliefconductorwidth=0.254 reliefentries=4 polygonreliefangle="90 Angle" airgapwidth=0.254
PolygonConnect PolygonConnect_11 [All vs IsNamedPolygon('TOP_LAYER_NONET_P089') Or  IsNamedPolygon('TOP_LAYER_NONET_P090')] p77: connectstyle=Direct reliefconductorwidth=0.254 reliefentries=4 polygonreliefangle="90 Angle" airgapwidth=0.254
PolygonConnect PolygonConnect_10 [All vs IsNamedPolygon('BOTTOM_LAYER_EZFET_USB_SHIELD_P002') Or  IsNamedPolygon('TOP_LAYER_EZFET_USB_SHIELD_P201') Or  IsNamedPolygon('SIGNAL_LAYER_2_EZFET_VBUS_P018') Or  IsNamedPolygon('SIGNAL_LAYER_2_EZFET_VCC_P016')] p78: connectstyle=Direct reliefconductorwidth=0.254 reliefentries=4 polygonreliefangle="90 Angle" airgapwidth=0.254
PolygonConnect PolygonConnect_9 [All vs IsNamedPolygon('TOP_LAYER_VM_P123') Or  IsNamedPolygon('TOP_LAYER_VM_P123') Or  IsNamedPolygon('TOP_LAYER_VM_P123')] p79: connectstyle=Direct reliefconductorwidth=0.254 reliefentries=4 polygonreliefangle="90 Angle" airgapwidth=0.254
PolygonConnect PolygonConnect_8 [All vs IsNamedPolygon('TOP_LAYER_NONET_P072')] p80: connectstyle=Direct reliefconductorwidth=0.254 reliefentries=4 polygonreliefangle="90 Angle" airgapwidth=0.254
PolygonConnect PolygonConnect_7 [All vs IsNamedPolygon('TOP_LAYER_NONET_P072')] p81: connectstyle=Direct reliefconductorwidth=0.254 reliefentries=4 polygonreliefangle="90 Angle" airgapwidth=0.254
PolygonConnect PolygonConnect_6 [All vs IsNamedPolygon('TOP_LAYER_VM_P042')] p82: connectstyle=Direct reliefconductorwidth=0.254 reliefentries=4 polygonreliefangle="90 Angle" airgapwidth=0.254
PolygonConnect PolygonConnect_5 [All vs IsNamedPolygon('TOP_LAYER_VM_P044')] p83: connectstyle=Direct reliefconductorwidth=0.254 reliefentries=4 polygonreliefangle="90 Angle" airgapwidth=0.254
PolygonConnect PolygonConnect_4 [All vs IsNamedPolygon('TOP_LAYER_VM_P046')] p84: connectstyle=Direct reliefconductorwidth=0.254 reliefentries=4 polygonreliefangle="90 Angle" airgapwidth=0.254
PolygonConnect PolygonConnect_3 [All vs IsNamedPolygon('TOP_LAYER_GND_P036') Or  IsNamedPolygon('TOP_LAYER_OUT2_P040') Or  IsNamedPolygon('TOP_LAYER_OUT1_P038')] p85: connectstyle=Direct reliefconductorwidth=0.254 reliefentries=4 polygonreliefangle="90 Angle" airgapwidth=0.254
PolygonConnect PolygonConnect_2 [InNet('EZFET_VBUS') vs IsNamedPolygon('TOP_LAYER_EZFET_VBUS_P008')] p86: connectstyle=Direct reliefconductorwidth=0.254 reliefentries=4 polygonreliefangle="90 Angle" airgapwidth=0.254
PolygonConnect PolygonConnect_1 [InNetClass('Power-Net') vs IsNamedPolygon('TOP_LAYER_EZFET_USB_SHIELD_P201')] p87: connectstyle=Direct reliefconductorwidth=0.254 reliefentries=4 polygonreliefangle="90 Angle" airgapwidth=0.254
PolygonConnect [All] p88: connectstyle=Relief reliefconductorwidth=0.254 reliefentries=4 polygonreliefangle="90 Angle" airgapwidth=0.254
RoutingVias ThermalPadVias [IsVia and InAnyComponent] p1: holewidth=0.2 width=0.5 viastyle="Through Hole" minholewidth=0.2 minwidth=0.5 maxholewidth=0.33 maxwidth=0.6
RoutingVias [All] p2: holewidth=0.406 width=0.864 viastyle="Through Hole" minholewidth=0.2 minwidth=0.66 maxholewidth=1.016 maxwidth=1.651
SilkToBoardRegionClearance [Not ((IsComment or IsDesignator) And (Hide <> 'False')) and not InRegion(1000,500,4000,800)] p1:
SilkToSilkClearance SilkToSilkClearance_Pb-FreeLogo [(HasFootprint('Pb-Free_Overlay_Medium') OR HasFootprint('Pb-Free_Overlay_Small')) vs (HasFootprint('Pb-Free_Overlay_Medium') OR HasFootprint('Pb-Free_Overlay_Small'))] p1: silktosilkclearance=0
SilkToSilkClearance [All] p2: silktosilkclearance=0.1
SilkToSolderMaskClearance SilkToComponentPadClearance [(IsPad or IsFill or IsRegion) and InAnycomponent] p1: minsilkscreentomaskgap=0.127 clearancetoexposedcopper=TRUE
SilkToSolderMaskClearance "Silk to Solder Mask Opening" [All] p2: minsilkscreentomaskgap=0.1 clearancetoexposedcopper=FALSE
SolderMaskExpansion [All] p1: expansion=0.05
UnRoutedNet [All] p1: checkbadconnections=TRUE
Width [All] p1: maxlimit=2.54 minlimit=0.152 preferedwidth=0.254 checkconnectedcopper=TRUE
14 further rules are at their usual default settings.

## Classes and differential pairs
net class Power-Net: 3V3_MCU EZFET_VBUS EZFET_VCC GND
component class Header: J2 J4 J5 J7 J10 J11 J12 J13
component class ezFET: C19 C20 C21 C22 C23 C24 C25 C26 C27 C28 C29 C30 C31 C32 C33 C34 C35 C36 C37 C44 C45 C47 C48 C49 C50 D5 D6 J5 J6 J7 L2 L3 R32 R33 R34 R35 R36 R37 R38 R41 R42 R43 R44 R45 R46 R47 R48 R49 R50 R51 U5 U6 U7 Y1
component class Logo: Logo2
component class FiducialMark: FID1 FID2 FID3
